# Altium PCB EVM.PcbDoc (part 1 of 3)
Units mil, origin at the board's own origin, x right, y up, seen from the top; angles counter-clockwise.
Board outline 4950 x 3450 mil, 6 copper layers (Top Layer, Power Layer 1 (PWR), Power Layer 2 (GND), Power Layer 3 (PWR), Power Layer 4 (GND), Bottom Layer), stack 58.4 mil thick; 378 components, 191 nets, 2749 pads, 0 vias.
Unrouted connection lines stored in the file: 482.
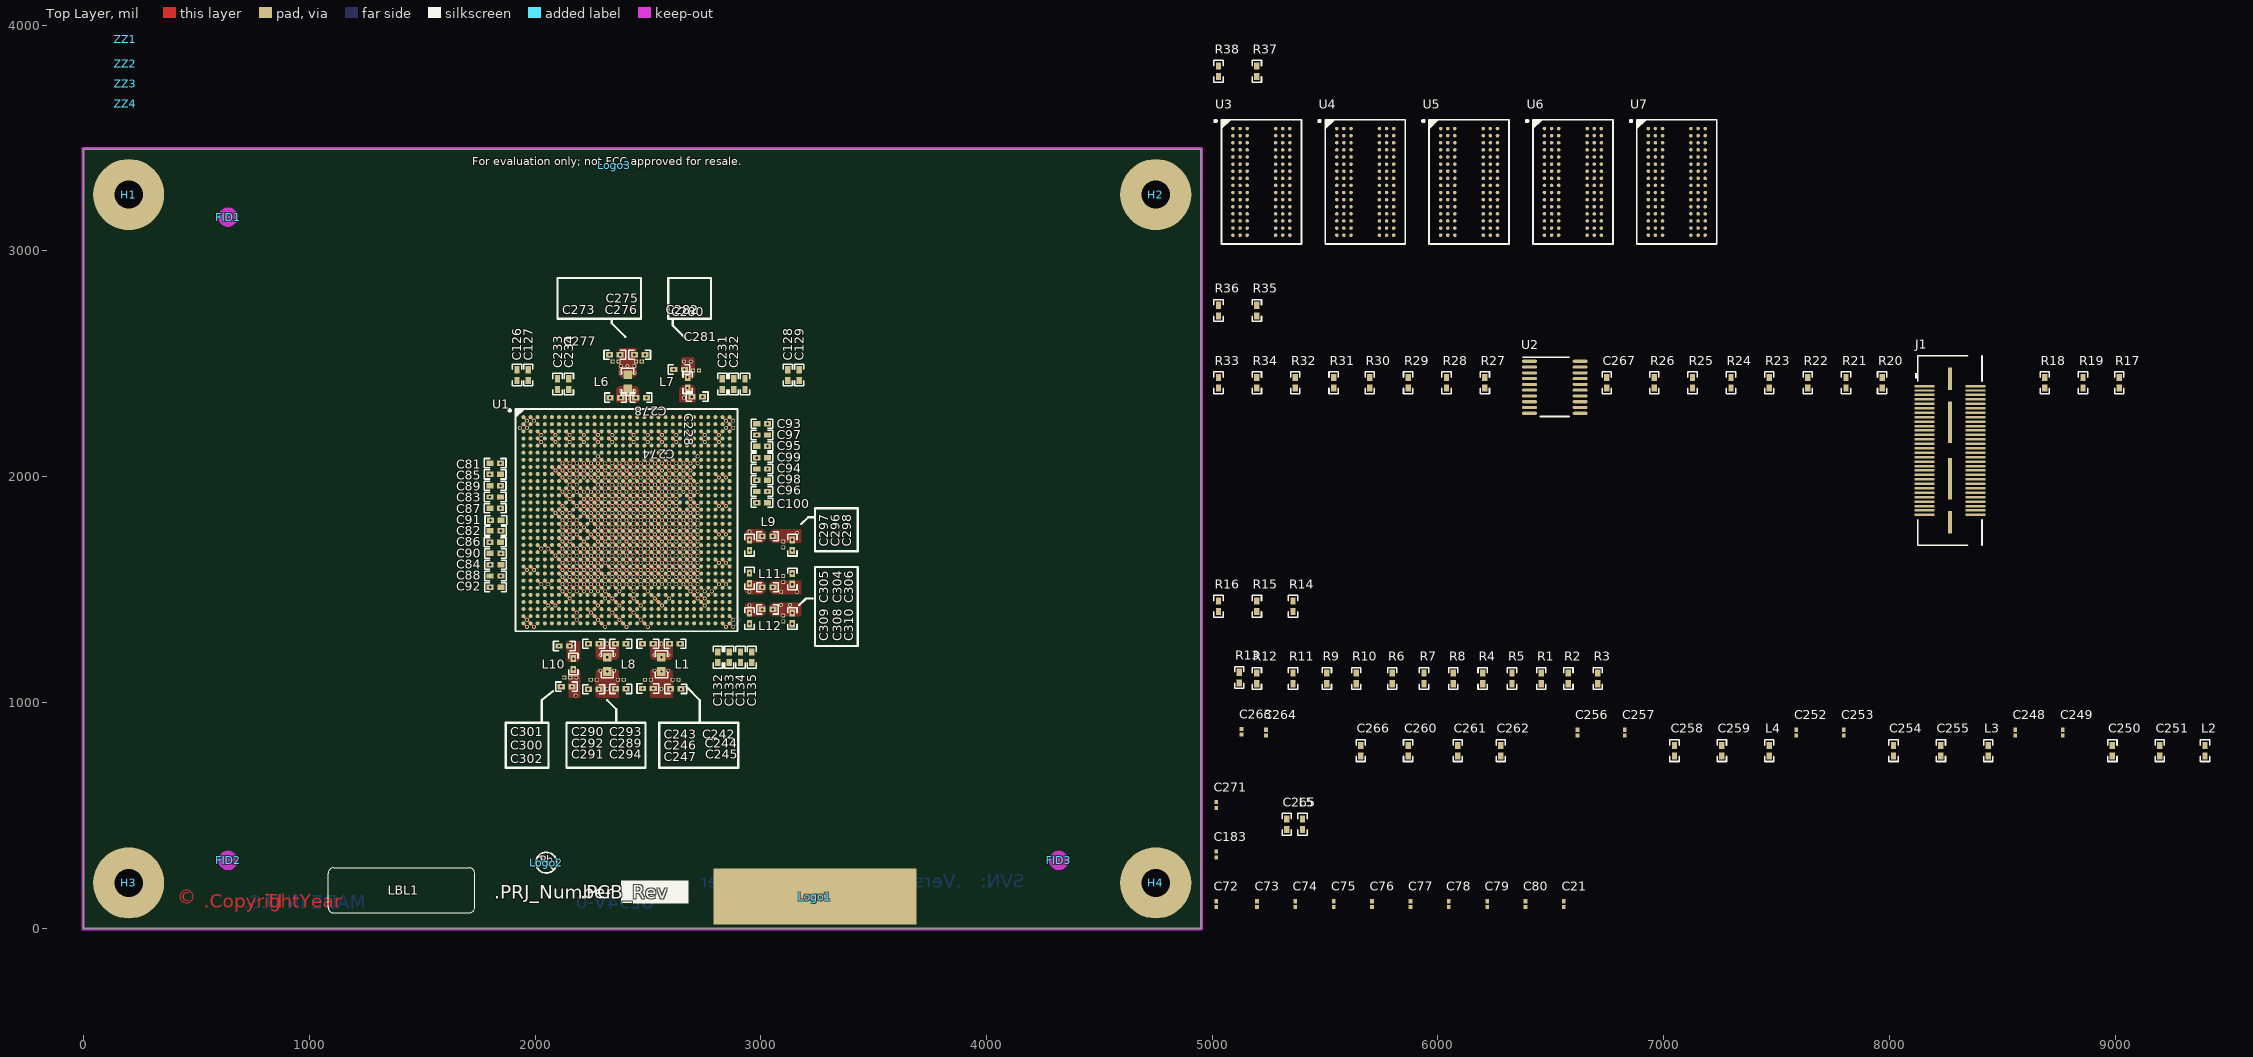
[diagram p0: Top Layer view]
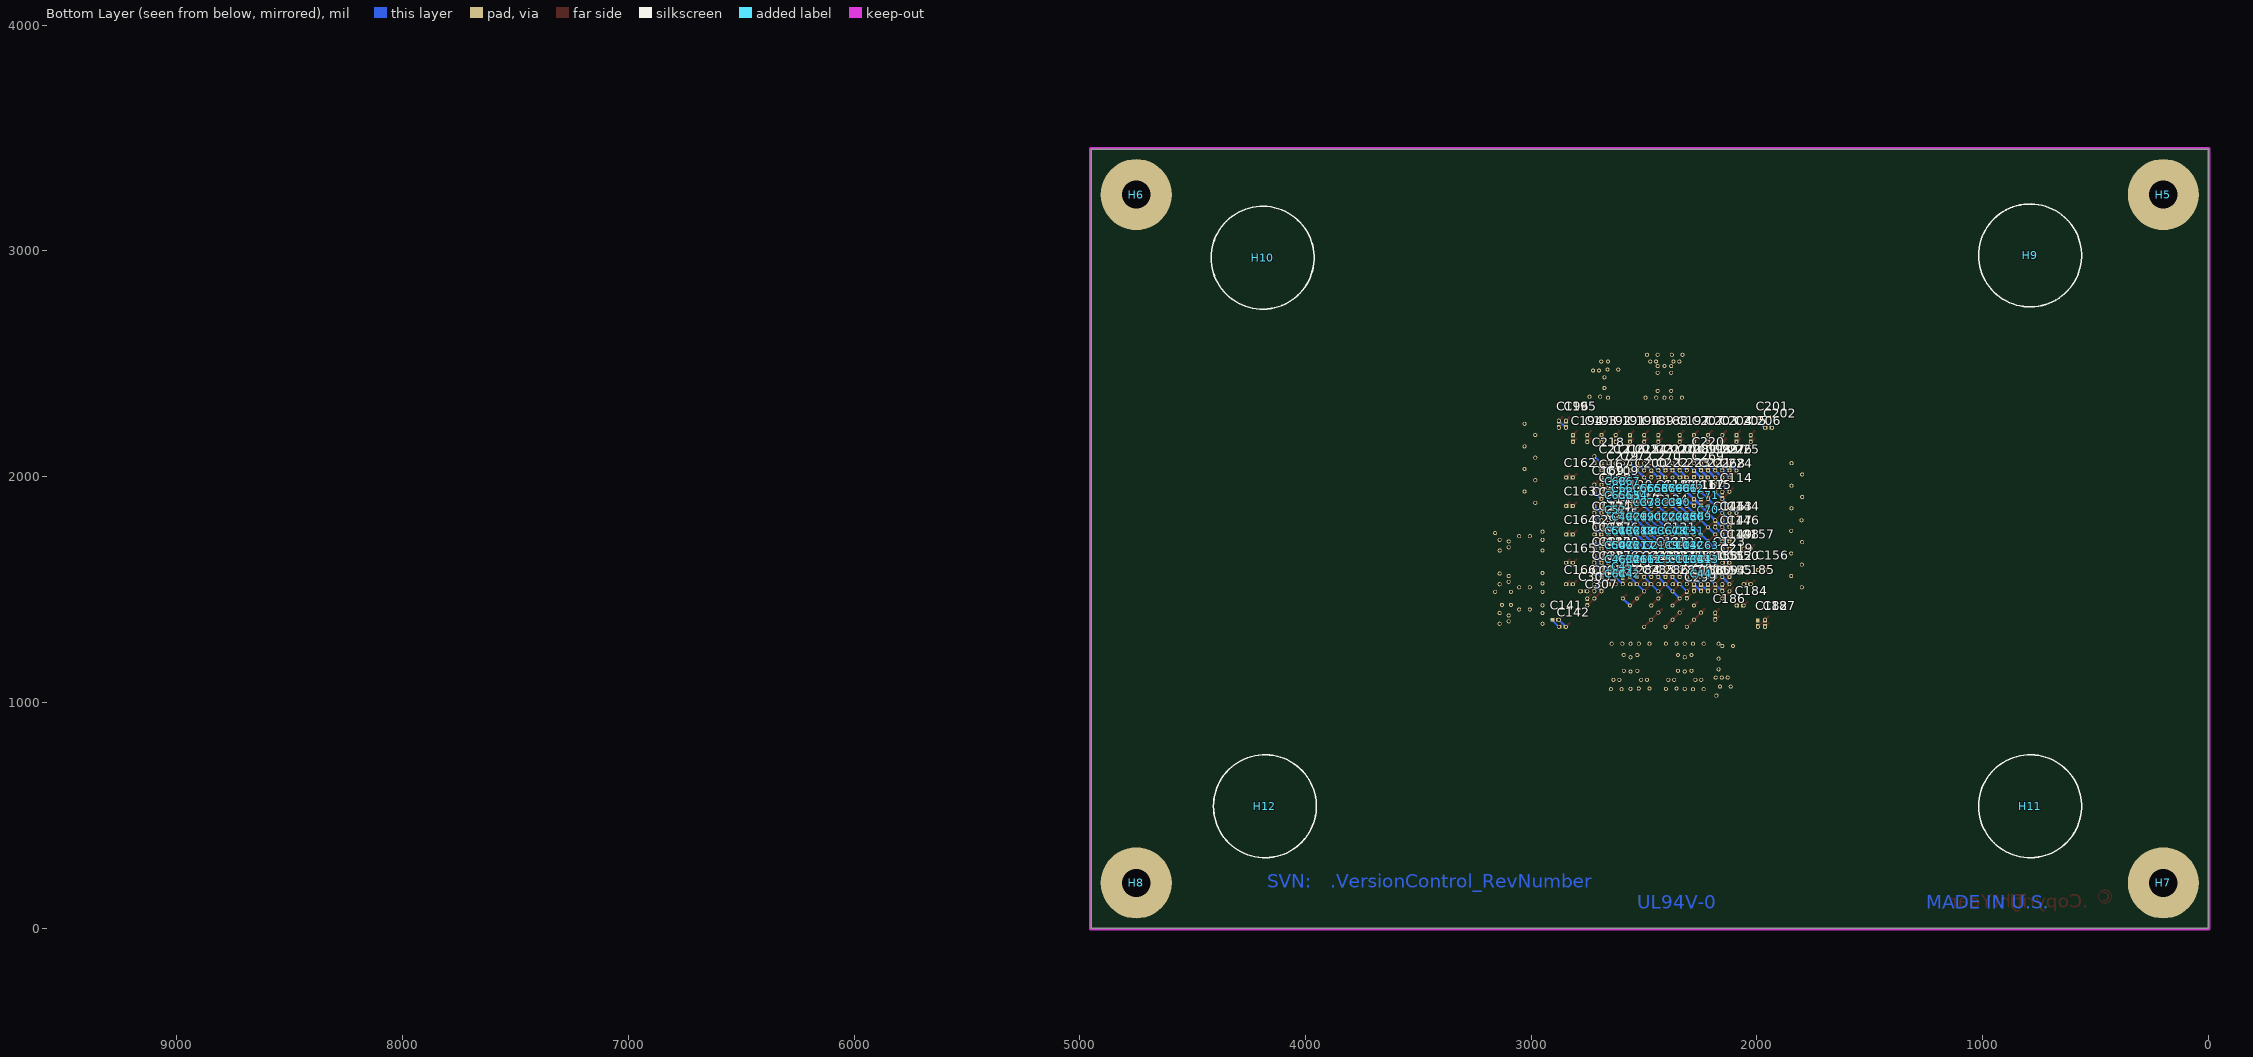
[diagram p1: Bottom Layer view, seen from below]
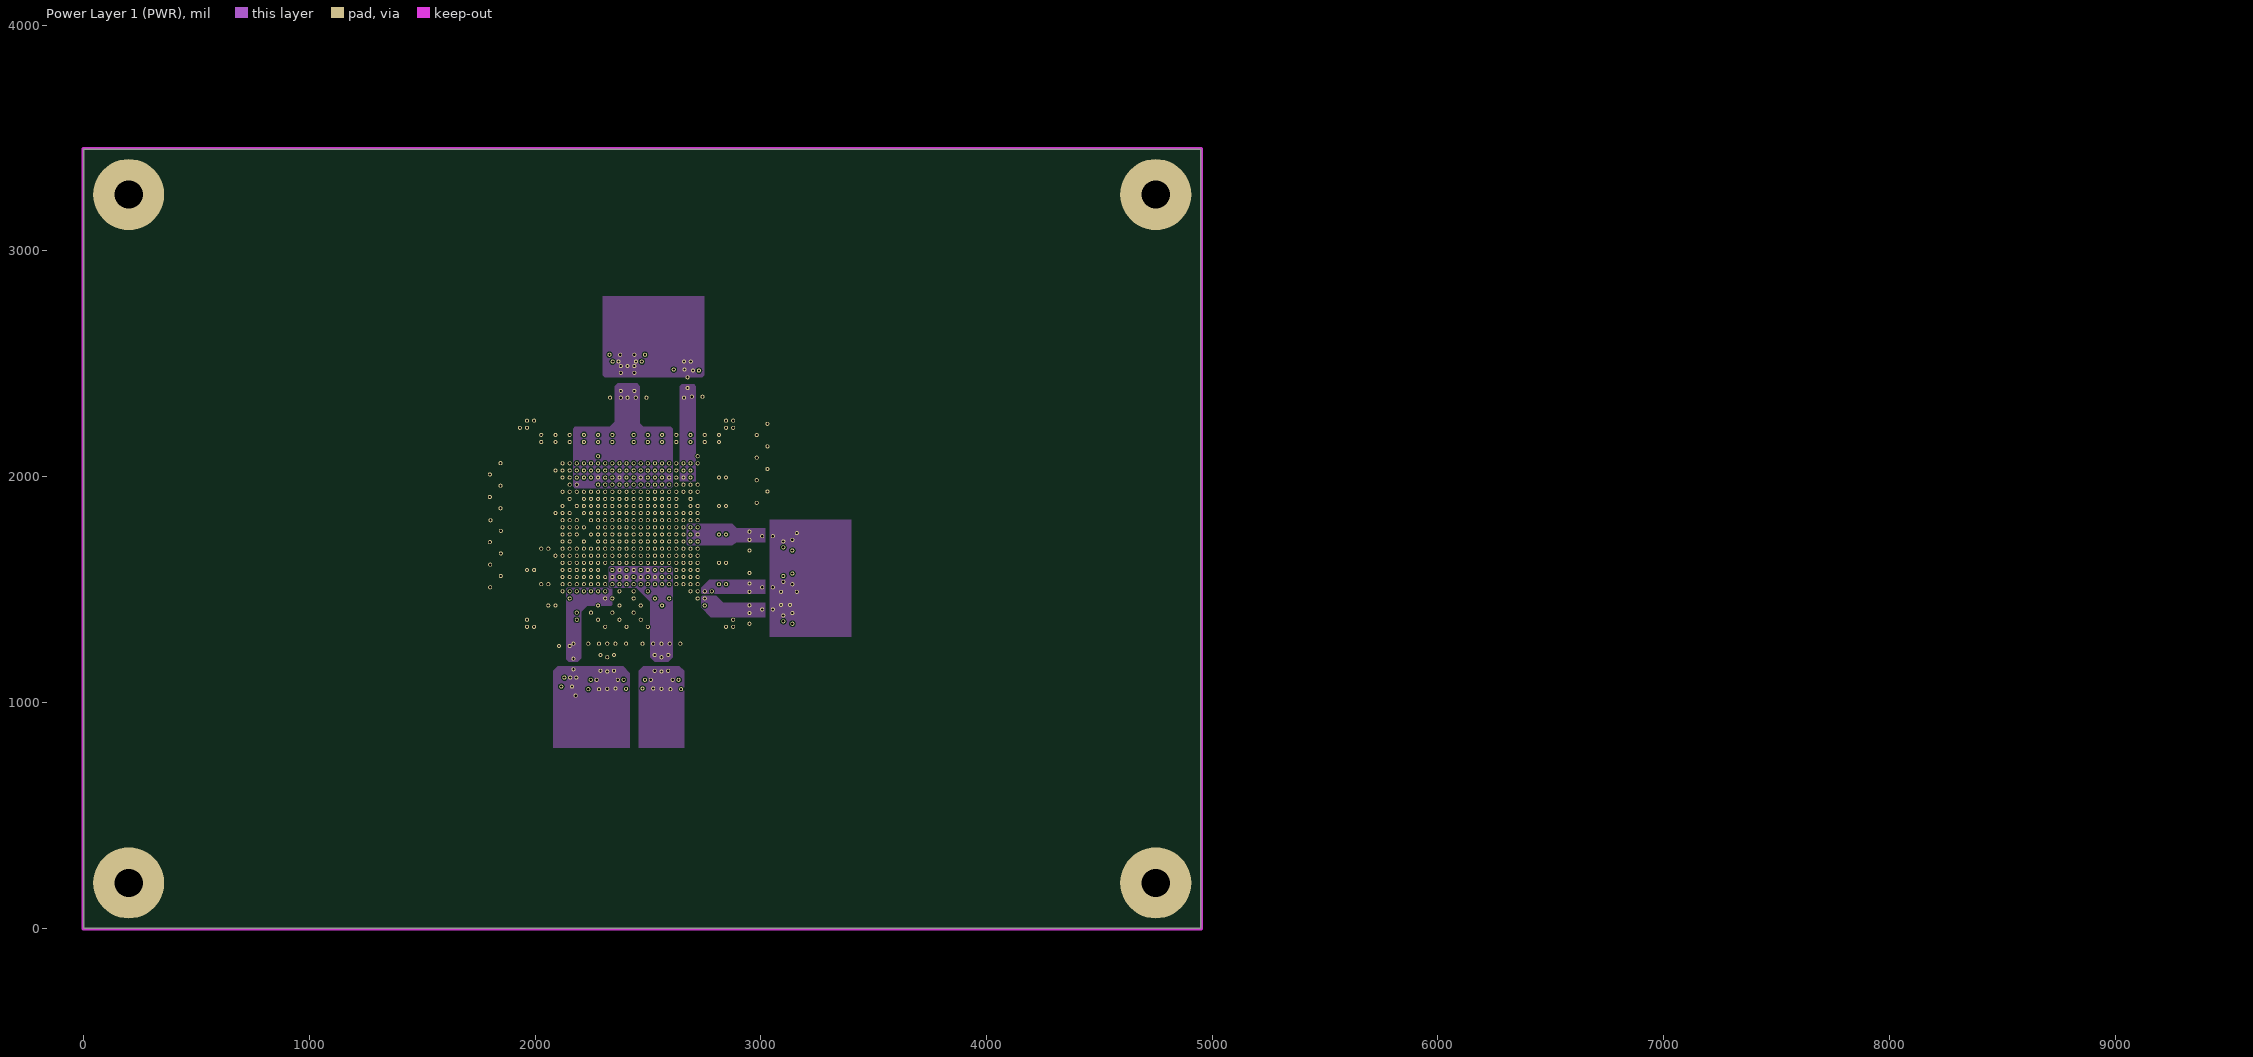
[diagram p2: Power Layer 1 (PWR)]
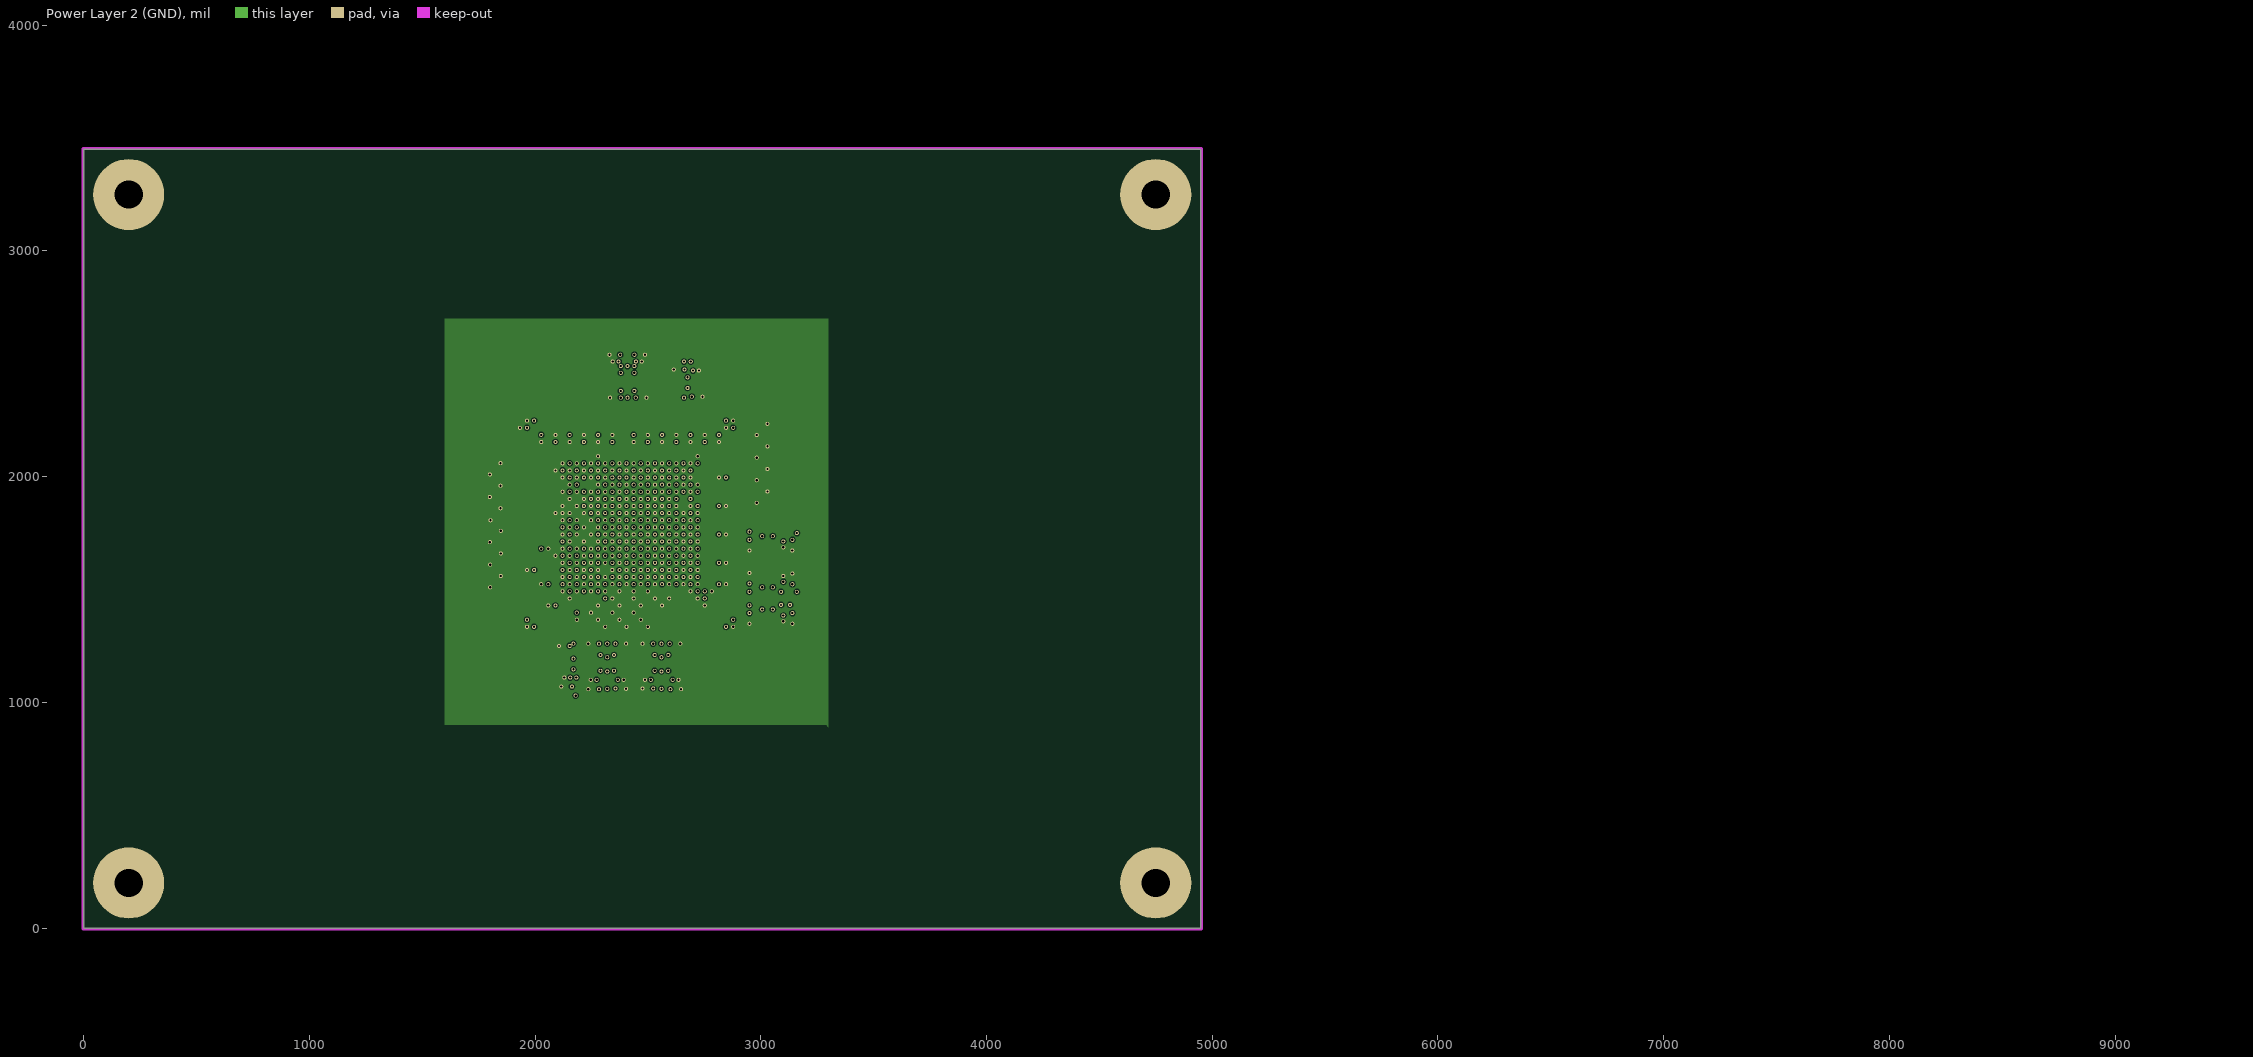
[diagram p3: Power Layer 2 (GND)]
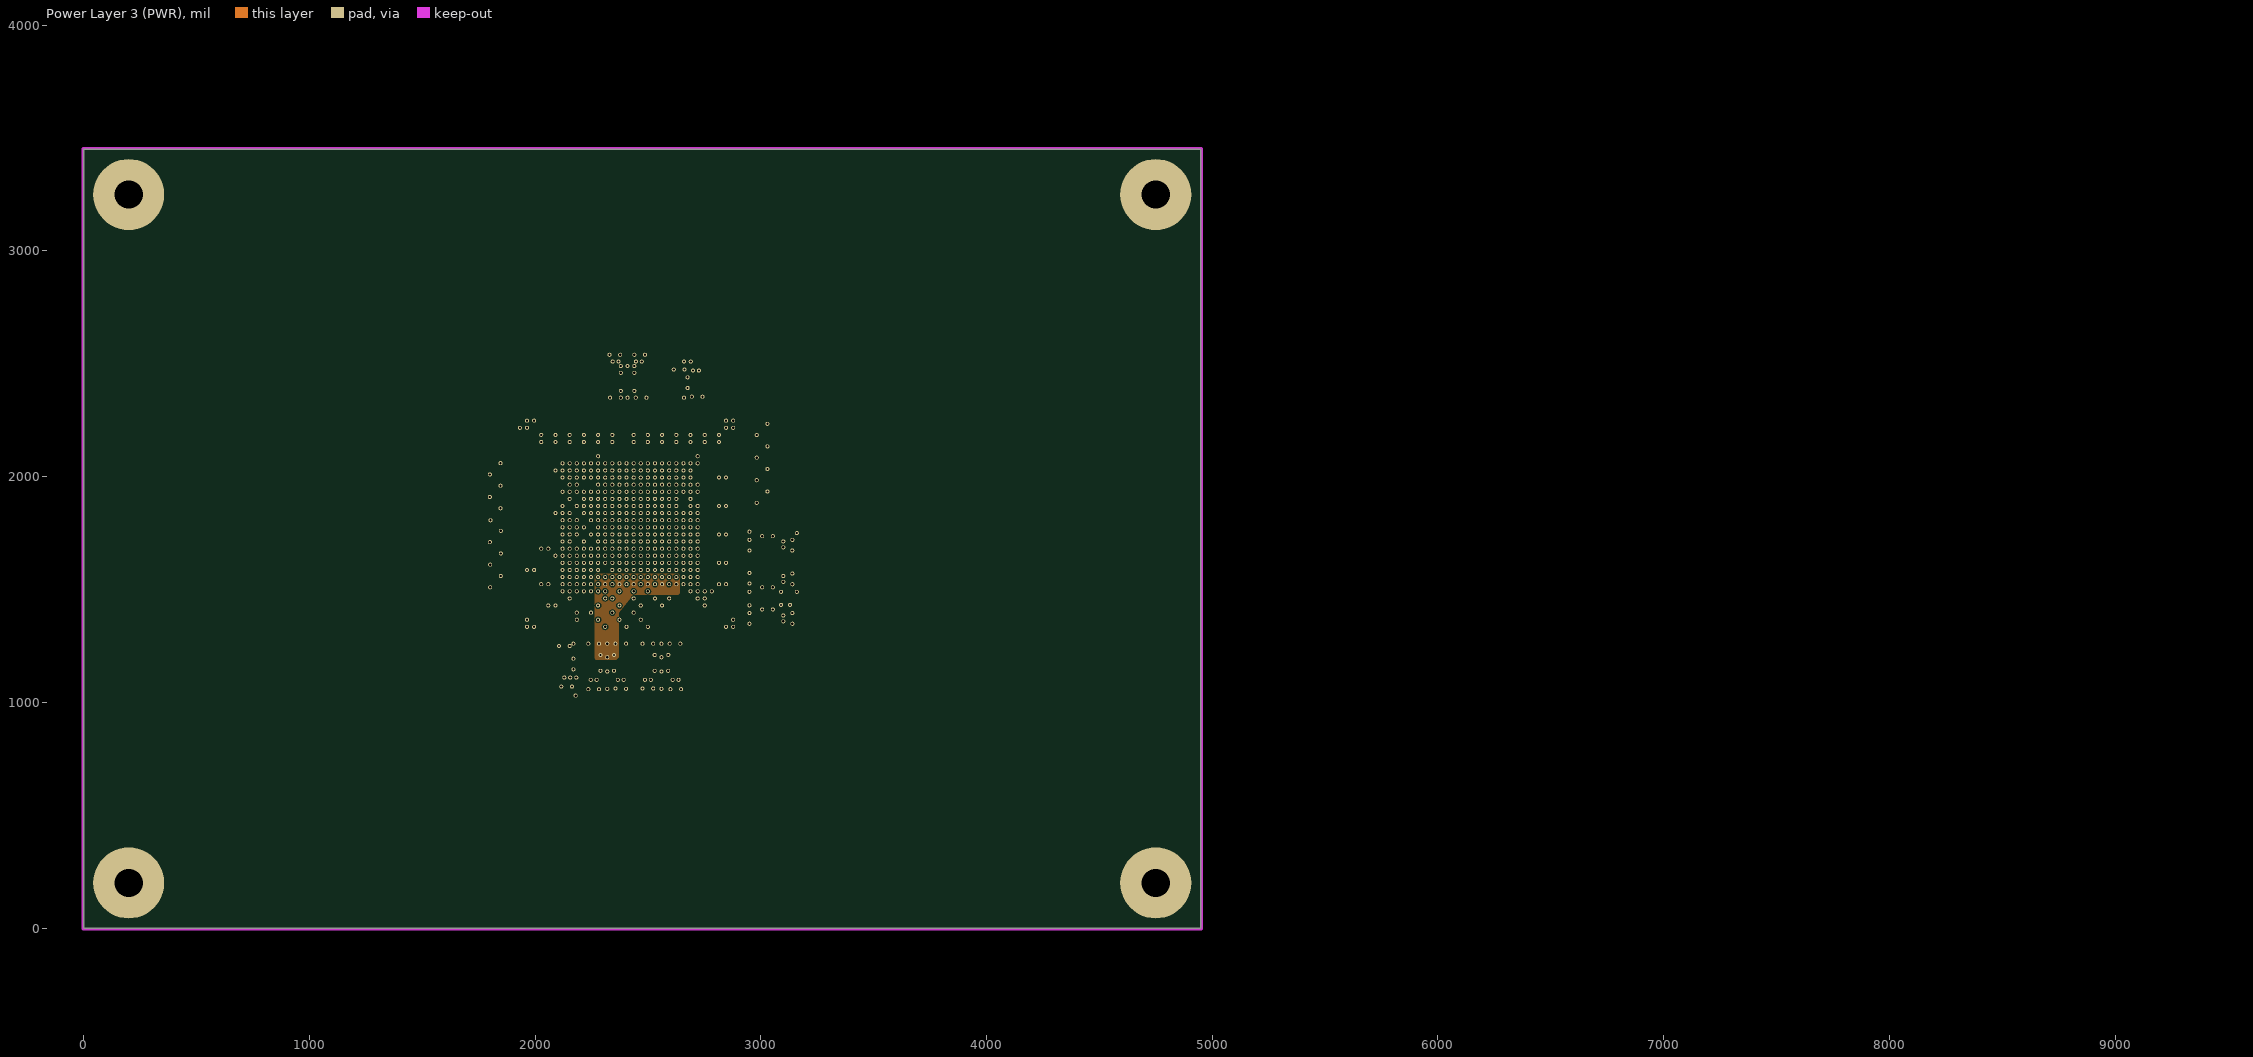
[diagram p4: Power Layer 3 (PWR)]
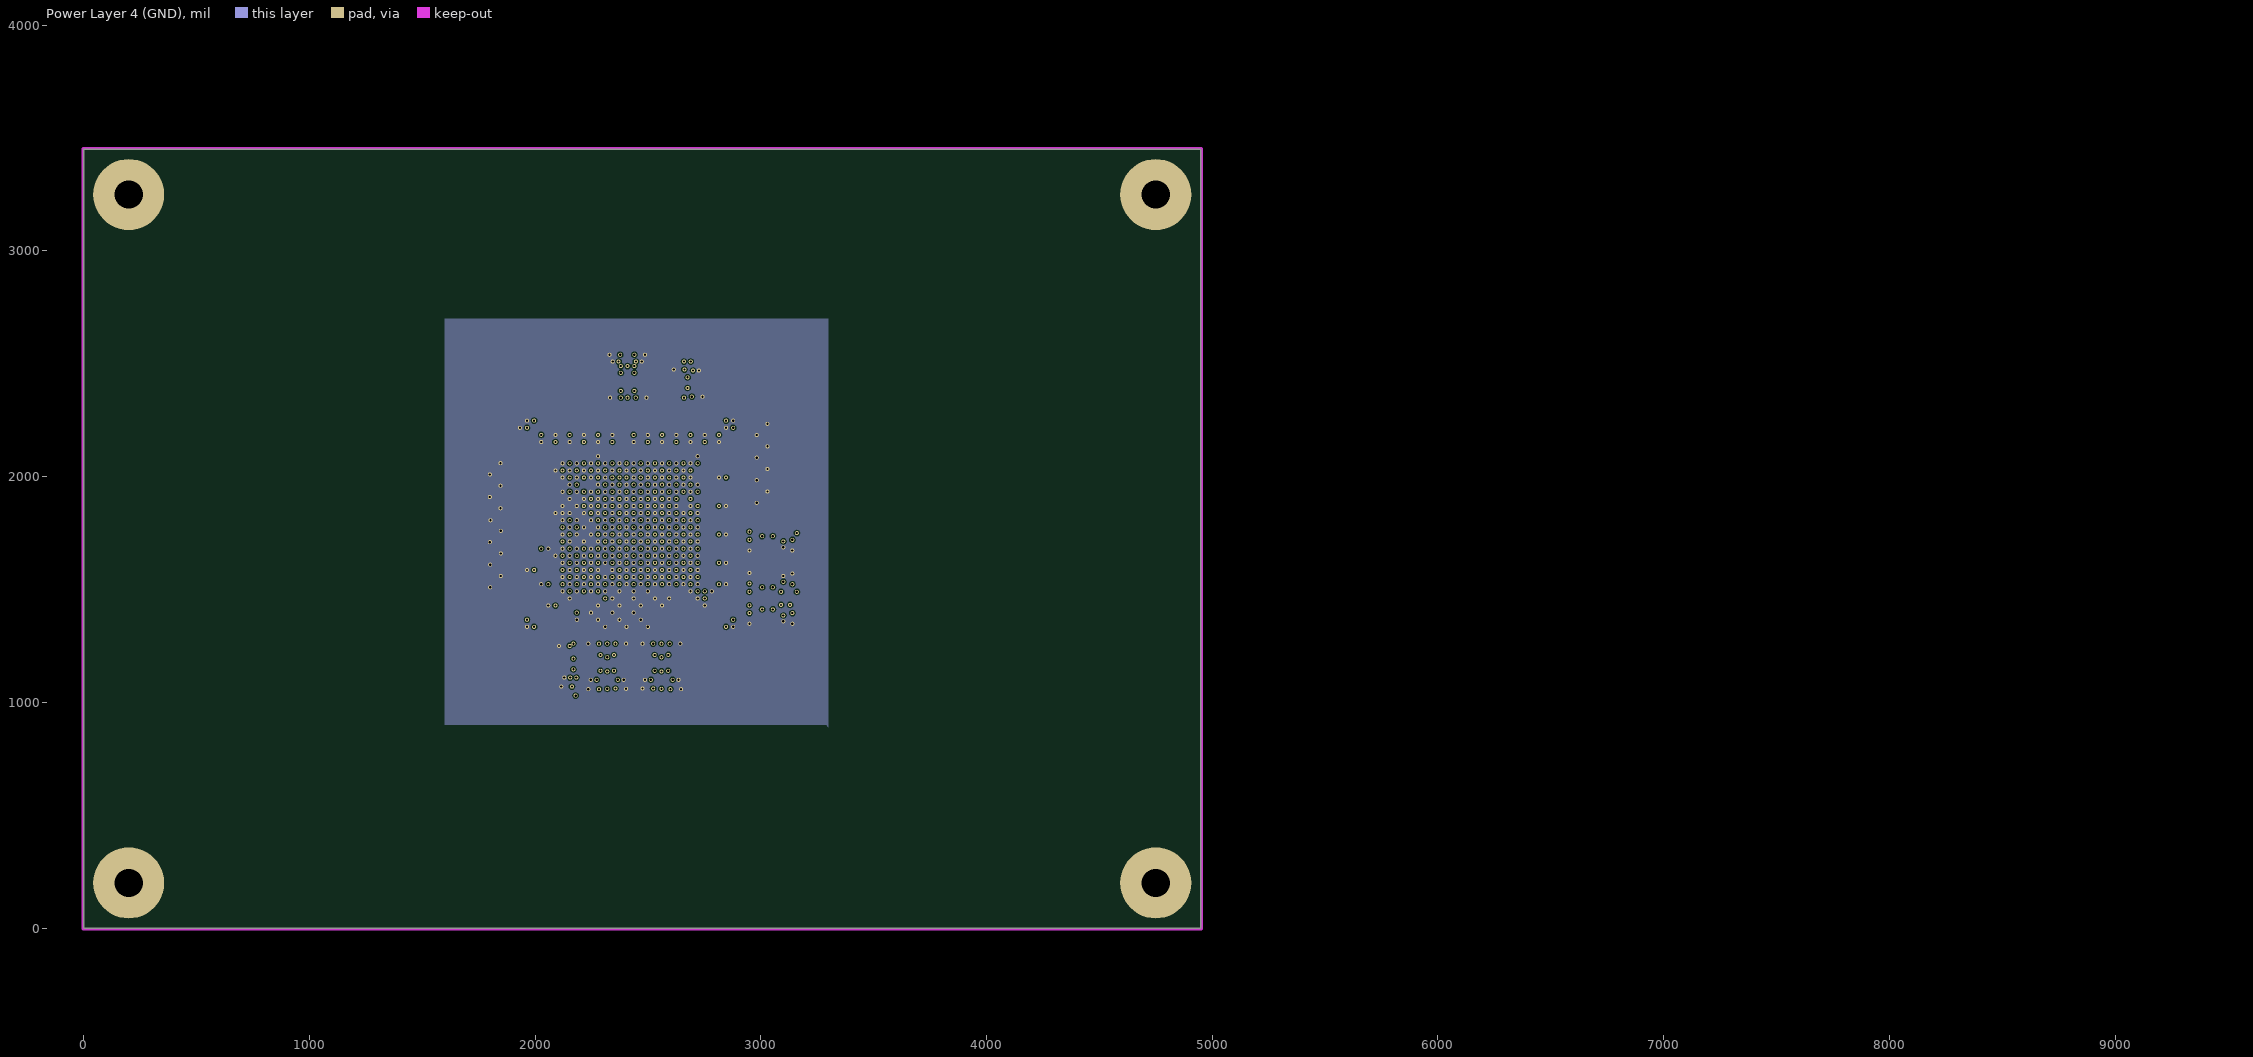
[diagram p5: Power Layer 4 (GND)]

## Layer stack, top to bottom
Top Solder: solder mask 0.4, Solder Resist, Dk 3.5
Top Layer: signal copper 1.4
Dielectric1: core 10, FR-4, Dk 4.8
Power Layer 1 (PWR): signal copper 1.4
Dielectric2: prepreg 10, FR-4, Dk 4.2
Power Layer 2 (GND): signal copper 1.4
Dielectric3: core 10, FR-4, Dk 4.2
Power Layer 3 (PWR): signal copper 1.4
Dielectric4: prepreg 10, FR-4, Dk 4.2
Power Layer 4 (GND): signal copper 1.4
Dielectric5: core 10, FR-4, Dk 4.2
Bottom Layer: signal copper 1.4
Bottom Solder: solder mask 0.4, Solder Resist, Dk 3.5

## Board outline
0,0 4950,0 4950,3450 0,3450

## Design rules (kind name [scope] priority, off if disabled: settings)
AcuteAngle [All] p1: minimum=4.50000000000000E+0001 checktracksonly=FALSE
AssemblyTestPointUsage [All] p1: valid=2
Clearance Clearance_Keepouts_0201_BGA_cap [(OnLayer('Top Layer') OR OnLayer('Bottom Layer')) vs (HasFootprint('0201') AND ( InNet('GND')OR InNet('K2L_CVDD') OR InNet('K2L_CVDD1V0')OR InNet('K2L_DVDD1V8')OR InNet('K2L_AVDDA1_1V8_FILT') OR InNet('K2L_AVDDA2_1V8_FILT') OR InNet('K2L_AVDDA3_1V8_FILT') OR InNet('K2L_AVDDA4_1V8_FILT') OR InNet('K2L_AVDDA5_1V8_FILT') OR InNet('K2L_AVDDA10_6_1V8_FILT') OR InNet('K2L_VDDAHV_1V8_FILT') OR InNet('K2L_VDDALV_FILT') OR   InNet('K2L_DVDD1V5')  )   )] p1: gap=0
Clearance Clearance_Keepouts_BGA900_0p80mm_pitch [(OnLayer('Top Layer') OR OnLayer('Bottom Layer') OR OnLayer('Multi-Layer') ) vs HasFootprint('BGA900C80P30X30_2500X2500X355')] p2: gap=3.94
Clearance Clearance_Keepouts [((IsTrack Or IsArc) And Not InPoly) And IsFree and IsKeepOut vs ((IsTrack Or IsArc) And Not InPoly) And IsFree and IsKeepOut] p3: gap=0
Clearance Clearance_BoardEdge_MountingHoles [OnCopper and InComponentClass('Mounting Holes') vs IsKeepOut] p4: gap=40
Clearance Clearance_BoardEdge_Poly [OnCopper and InPoly vs IsKeepOut] p5: gap=25
Clearance Clearance_BoardEdge [OnCopper and Not InComponentClass('Logo') and not InComponentClass('FiducialMark') and not InRegion(1000,500,4000,800) and Not IsKeepout vs IsKeepOut] p6: gap=75
Clearance Clearance_Poly1 [InPolygon vs InNet('GND')OR InNet('K2L_CVDD') OR InNet('K2L_CVDD1V0')OR InNet('K2L_DVDD1V8')OR InNet('K2L_AVDDA1_1V8_FILT') OR InNet('K2L_AVDDA2_1V8_FILT') OR InNet('K2L_AVDDA3_1V8_FILT') OR InNet('K2L_AVDDA4_1V8_FILT') OR InNet('K2L_AVDDA5_1V8_FILT') OR InNet('K2L_AVDDA10_6_1V8_FILT') OR InNet('K2L_VDDAHV_1V8_FILT') OR InNet('K2L_VDDALV_FILT') OR InNet('K2L_DVDD0V85') OR    InNet('K2L_DVDD1V5')] p7: gap=5
Clearance Clearance_Poly2 [InPolygon] p8: gap=25
Clearance [All] p9: gap=3.94
ComponentClearance ComponentClearance_MountingHoles_FiducialMarks [InComponentClass('Mounting Holes') vs InComponentClass('FiducialMark')] p1: gap=50 collisioncheckmode=3 verticalgap=10 showdistances=FALSE
ComponentClearance ComponentClearance_Shunt [InComponentClass('Header') vs InComponentClass('Shunt')] p2: gap=0 collisioncheckmode=3 verticalgap=0 showdistances=FALSE
ComponentClearance ComponentClearance_Logo [InComponentClass('Logo')] p3: gap=50 collisioncheckmode=3 verticalgap=10 showdistances=FALSE
ComponentClearance ComponentClearance_ScrewToNut [(HasFootprint('NY PMS 440 0025 PH')) vs (HasFootprint('Keystone_1902C'))] p4: gap=5 collisioncheckmode=3 verticalgap=10 showdistances=FALSE
ComponentClearance ComponentClearance_MountingHoles [InComponentClass('Mounting Holes')] p5: gap=250 collisioncheckmode=3 verticalgap=100000 showdistances=FALSE
ComponentClearance ComponentClearance_SmallPassives [HasFootprint('0201*') or HasFootprint('0402*') or HasFootprint('0508') or HasFootprint('0603*') or HasFootprint('0612') or HasFootprint('0805*') or HasFootprint('0815*') or HasFootprint('0830*') or HasFootprint('1206*') or HasFootprint('1210*') or HasFootprint('1808*') or HasFootprint('1812*') or HasFootprint('1825*') or HasFootprint('2010*') or HasFootprint('2220*') or HasFootprint('2225*') or HasFootprint('2512*') or HasFootprint('2728*') or HasFootprint('3518*') vs HasFootprint('0201*') or HasFootprint('0402*') or HasFootprint('0508') or HasFootprint('0603*') or HasFootprint('0612') or HasFootprint('0805*') or HasFootprint('0815*') or HasFootprint('0830*') or HasFootprint('1206*') or HasFootprint('1210*') or HasFootprint('1808*') or HasFootprint('1812*') or HasFootprint('1825*') or HasFootprint('2010*') or HasFootprint('2220*') or HasFootprint('2225*') or HasFootprint('2512*') or HasFootprint('2728*') or HasFootprint('3518*')] p6: gap=10 collisioncheckmode=3 verticalgap=10 showdistances=FALSE
ComponentClearance ComponentClearance_THtoSMT [IsThruComponent vs IsSMTComponent] p7: gap=100 collisioncheckmode=3 verticalgap=30 showdistances=FALSE
ComponentClearance ComponentClearance_THtoTH [IsThruComponent vs IsThruComponent] p8: gap=118.11 collisioncheckmode=3 verticalgap=30 showdistances=FALSE
ComponentClearance [All] p9: gap=40 collisioncheckmode=3 verticalgap=10 showdistances=FALSE
DiffPairsRouting [All] p1: maxlimit=100 minlimit=10 mostfreqgap=10 toplayer_minwidth=15 toplayer_maxwidth=15 toplayer_prefwidth=15 midlayer1_minwidth=15 midlayer1_maxwidth=15 midlayer1_prefwidth=15 midlayer2_minwidth=15 midlayer2_maxwidth=15 midlayer2_prefwidth=15 midlayer3_minwidth=15 midlayer3_maxwidth=15 midlayer3_prefwidth=15 midlayer4_minwidth=15 midlayer4_maxwidth=15 midlayer4_prefwidth=15 bottomlayer_minwidth=15 bottomlayer_maxwidth=15 bottomlayer_prefwidth=15 maxuncoupledlength=1000
FabricationTestPointUsage TestPointUsage [All] p1: valid=2 allowmultiple=FALSE
FabricationTestpoint Testpoint [All] p1: side=3 testpointundercomponent=TRUE minsize=40 maxsize=100 preferedsize=60 minholesize=0 maxholesize=40 preferedholesize=32 testpointgrid=1 allowsidetop=TRUE allowsidebottom=TRUE usegrid=TRUE gridtolerance=0.01
FanoutControl Fanout_LCC [IsLCC] p1: bgadir=Out bgaviamode=Centered fanoutstyle=Auto fanoutdirection=Alternating viagrid=1 // Fanout_LCC (Default Rule)
FanoutControl Fanout_BGA [IsBGA] p2: bgadir=Out bgaviamode=Centered fanoutstyle=Auto fanoutdirection=Alternating viagrid=1 // Fanout_BGA (Default Rule)
FanoutControl Fanout_Default [All] p4: bgadir=Out bgaviamode=Centered fanoutstyle=Auto fanoutdirection=Alternating viagrid=1 // Fanout_Default (Default Rule)
FanoutControl Fanout_Small [(CompPinCount < 5)] p5: bgadir=Out bgaviamode=Centered fanoutstyle=Auto fanoutdirection=OutThenIn viagrid=1 // Fanout_Small (Default Rule)
HoleSize [All] p1: absolutevalues=TRUE maxlimit=251 minlimit=8 maxpercent=80.000 minpercent=20.000
MinimumAnnularRing MinimumAnnularRing_ThermalPadVias [IsVia and InAnyComponent] p1: minimumring=5.91
MinimumAnnularRing [All] p2: minimumring=9
MinimumSolderMaskSliver MinimumSolderMaskSliver_Logo [InComponentClass('Logo') vs InComponentClass('Logo')] p1: minsoldermaskwidth=0.7
MinimumSolderMaskSliver [All] p2: minsoldermaskwidth=3.94
PlaneClearance [All] p1: clearance=10
PlaneConnect [All] p1: planeconnectstyle=Direct reliefexpansion=10 reliefentries=4 reliefconductorwidth=10 reliefairgap=10
PolygonConnect [All] p1: connectstyle=Direct reliefconductorwidth=10 reliefentries=4 polygonreliefangle="90 Angle" airgapwidth=10
RoutingVias ThermalPadVias [IsVia and InAnyComponent] p1: holewidth=7.87 width=19.68 viastyle="Through Hole" minholewidth=7.87 minwidth=19.68 maxholewidth=12.99 maxwidth=23.62
RoutingVias [All] p2: holewidth=16 width=34 viastyle="Through Hole" minholewidth=7.87 minwidth=26 maxholewidth=40 maxwidth=65
SilkToBoardRegionClearance [Not ((IsComment or IsDesignator) And (Hide <> 'False')) and not InRegion(1000,500,4000,800)] p1:
SilkToSilkClearance SilkToSilkClearance_Pb-FreeLogo [(HasFootprint('Pb-Free_Overlay_Medium') OR HasFootprint('Pb-Free_Overlay_Small')) vs (HasFootprint('Pb-Free_Overlay_Medium') OR HasFootprint('Pb-Free_Overlay_Small'))] p1: silktosilkclearance=0
SilkToSilkClearance [All] p2: silktosilkclearance=5
SilkToSolderMaskClearance "Silk to Solder Mask Opening" [All] p1: minsilkscreentomaskgap=1 clearancetoexposedcopper=FALSE
SolderMaskExpansion [All] p1: expansion=1.97
UnpouredPolygon [All] p1: allowunpoured=FALSE
Width [All] p1: maxlimit=100 minlimit=6 preferedwidth=10 checkconnectedcopper=TRUE
13 further rules are at their usual default settings.

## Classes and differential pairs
component class k2l_soc_14: R37 R38
component class k2l_soc_09_1: U3 U4 U5 U6 U7
component class k2l_soc_08: R35 R36
component class k2l_soc_07: C267 J1 R17 R18 R19 R20 R21 R22 R23 R24 R25 R26 R27 R28 R29 R30 R31 R32 R33 R34 U2
component class k2l_soc_06: R14 R15 R16
component class k2l_soc_05: R1 R2 R3 R4 R5 R6 R7 R8 R9 R10 R11 R12 R13
component class k2l_soc_03_1: C268 C269 C270 C271 C272 C273 C274 C275 C276 C277 C278 C279 C280 C281 C282 C283 C284 C285 C286 C287 C288 C289 C290 C291 C292 C293 C294 C295 C296 C297 C298 C299 C300 C301 C302 C303 C304 C305 C306 C307 C308 C309 C310 L6 L7 L8 L9 L10 L11 L12
component class k2l_soc_04: C235 C236 C237 C238 C239 C240 C241 C242 C243 C244 C245 C246 C247 C248 C249 C250 C251 C252 C253 C254 C255 C256 C257 C258 C259 C260 C261 C262 C263 C264 C265 C266 L1 L2 L3 L4 L5
component class k2l_soc_03: C109 C110 C111 C112 C113 C114 C115 C116 C117 C118 C119 C120 C121 C122 C123 C124 C126 C127 C128 C129 C132 C133 C134 C135 C136 C137 C138 C139 C140 C141 C142 C143 C144 C145 C146 C147 C148 C149 C150 C151 C152 C153 C154 C155 C156 C157 C158 C159 C160 C161 C162 C163 C164 C165 C166 C167 C168 C169 C170 C171 C172 C173 C174 C175 C176 C177 C178 C179 C180 C181 C182 C183 C184 C185 C186 C187 C188 C189 C190 C191 C192 C193 C194 C195 C196 C197 C198 C199 C200 C201 C202 C203 C204 C205 C206 C207 C208 C209 C210 C211 C212 C213 C214 C215 C216 C217 C218 C219 C220 C221 C222 C223 C224 C225 C226 C227 C228 C231 C232 C233 C234
component class k2l_soc_02: C1 C2 C3 C4 C5 C6 C7 C8 C9 C10 C11 C12 C13 C14 C15 C16 C17 C18 C19 C20 C21 C22 C23 C24 C25 C26 C27 C28 C29 C30 C31 C32 C33 C34 C35 C36 C37 C38 C39 C40 C41 C42 C43 C44 C45 C46 C47 C48 C49 C50 C51 C52 C53 C54 C55 C56 C57 C58 C59 C60 C61 C62 C63 C64 C65 C66 C67 C68 C69 C70 C71 C72 C73 C74 C75 C76 C77 C78 C79 C80 C81 C82 C83 C84 C85 C86 C87 C88 C89 C90 C91 C92 C93 C94 C95 C96 C97 C98 C99 C100
component class k2l_soc_01: U1
component class Label: LBL1
component class AssemblyNote: ZZ1 ZZ2 ZZ3 ZZ4
component class FiducialMark: FID1 FID2 FID3
component class EVM_Hardware: FID1 FID2 FID3 H1 H2 H3 H4 H5 H6 H7 H8 H9 H10 H11 H12 LBL1 Logo1 Logo2 Logo3 ZZ1 ZZ2 ZZ3 ZZ4
component class Logo: Logo1
component class "Mounting Holes": H1 H2 H3 H4

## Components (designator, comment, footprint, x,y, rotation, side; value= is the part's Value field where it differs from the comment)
C1 "GRM033R71E102KA01D" 0201 2437.01,1696.85 r270 bottom
C2 "GRM033R71E102KA01D" 0201 2468.5,1696.85 r90 bottom
C3 "GRM033R71E102KA01D" 0201 2437.01,1759.84 r270 bottom
C4 "GRM033R71E102KA01D" 0201 2468.5,1759.84 r90 bottom
C5 "GRM033R71E102KA01D" 0201 2405.51,1633.86 r90 bottom
C6 "GRM033R71E102KA01D" 0201 2405.51,1759.84 r90 bottom
C7 "GRM033R71E102KA01D" 0201 2374.02,1759.84 r270 bottom
C8 "GRM033R71E102KA01D" 0201 2342.52,1759.84 r90 bottom
C9 "GRM033R71E102KA01D" 0201 2374.02,1696.85 r270 bottom
C10 "GRM033R71E102KA01D" 0201 2342.52,1696.85 r90 bottom
C11 "GRM033R71E102KA01D" 0201 2342.52,1633.86 r90 bottom
C12 "GRM033R71E102KA01D" 0201 2468.5,1633.86 r90 bottom
C13 "GRM033R71E102KA01D" 0201 2311.02,1633.86 r270 bottom
C14 "GRM033R71E102KA01D" 0201 2311.02,1696.85 r270 bottom
C15 "GRM033R71E102KA01D" 0201 2311.02,1759.84 r270 bottom
C16 "GRM033R71E102KA01D" 0201 2500,1633.86 r270 bottom
C17 "GRM033R71E102KA01D" 0201 2500,1696.85 r270 bottom
C18 "GRM033R71E102KA01D" 0201 2500,1759.84 r270 bottom
C19 "GRM033R71E102KA01D" 0201 2500,1822.83 r270 bottom
C20 "GRM033R71E102KA01D" 0201 2468.5,1822.83 r90 bottom
C21 "GRM033R71E102KA01D" 0201 6558,106 r90 top
C22 "GRM033R71E102KA01D" 0201 2405.51,1822.83 r90 bottom
C23 "GRM033R71E102KA01D" 0201 2374.02,1822.83 r270 bottom
C24 "GRM033R71E102KA01D" 0201 2342.52,1822.83 r90 bottom
C25 "GRM033R71E102KA01D" 0201 2311.02,1822.83 r270 bottom
C26 "GRM033R71E102KA01D" 0201 2531.5,1633.86 r90 bottom
C27 "GRM033R71E102KA01D" 0201 2531.5,1696.85 r90 bottom
C28 "GRM033R71E102KA01D" 0201 2531.5,1759.84 r90 bottom
C29 "GRM033R71E102KA01D" 0201 2531.5,1822.83 r90 bottom
C30 "GRM033R71E102KA01D" 0201 2279.53,1822.83 r90 bottom
C31 "GRM033R71E102KA01D" 0201 2279.53,1759.84 r90 bottom
C32 "GRM033R71E102KA01D" 0201 2279.53,1696.85 r90 bottom
C33 "GRM033R71E102KA01D" 0201 2279.53,1633.86 r90 bottom
C34 "GRM033R71E102KA01D" 0201 2562.99,1633.86 r270 bottom
C35 "GRM033R71E102KA01D" 0201 2562.99,1696.85 r270 bottom
C36 "GRM033R71E102KA01D" 0201 2562.99,1759.84 r270 bottom
C37 "GRM033R71E102KA01D" 0201 2500,1885.83 r270 bottom
C38 "GRM033R71E102KA01D" 0201 2468.5,1885.83 r90 bottom
C39 "GRM033R71E102KA01D" 0201 2374.02,1885.83 r270 bottom
C40 "GRM033R71E102KA01D" 0201 2342.52,1885.83 r90 bottom
C41 "GRM033R71E102KA01D" 0201 2248.03,1633.86 r270 bottom
C42 "GRM033R71E102KA01D" 0201 2562.99,1570.87 r270 bottom
C43 "GRM033R71E102KA01D" 0201 2216.54,1633.86 r90 bottom
C44 "GRM033R71E102KA01D" 0201 2248.03,1570.87 r270 bottom
C45 "GRM033R71E102KA01D" 0201 2594.49,1602.36 r270 bottom
C46 "GRM033R71E102KA01D" 0201 2625.98,1633.86 r270 bottom
C47 "GRM033R71E102KA01D" 0201 2594.49,1696.85 r90 bottom
C48 "GRM033R71E102KA01D" 0201 2594.49,1759.84 r90 bottom
C49 "GRM033R71E102KA01D" 0201 2594.49,1822.83 r90 bottom
C50 "GRM033R71E102KA01D" 0201 2625.98,1696.85 r270 bottom
C51 "GRM033R71E102KA01D" 0201 2625.98,1759.84 r270 bottom
C52 "GRM033R71E102KA01D" 0201 2625.98,1854.33 r90 bottom
C53 "GRM033R71E102KA01D" 0201 2562.99,1917.32 r90 bottom
C54 "GRM033R71E102KA01D" 0201 2531.5,1917.32 r270 bottom
C55 "GRM033R71E102KA01D" 0201 2468.5,1948.82 r90 bottom
C56 "GRM033R71E102KA01D" 0201 2500,1948.82 r270 bottom
C57 "GRM033R71E102KA01D" 0201 2405.51,1948.82 r90 bottom
C58 "GRM033R71E102KA01D" 0201 2437.01,1948.82 r270 bottom
C59 "GRM033R71E102KA01D" 0201 2374.02,1948.82 r270 bottom
C60 "GRM033R71E102KA01D" 0201 2342.52,1948.82 r90 bottom
C61 "GRM033R71E102KA01D" 0201 2311.02,1948.82 r270 bottom
C62 "GRM033R71E102KA01D" 0201 2279.53,1948.82 r90 bottom
C63 "GRM033R71E102KA01D" 0201 2216.54,1696.85 r90 bottom
C64 "GRM033R71E102KA01D" 0201 2625.98,1570.87 r270 bottom
C65 "GRM033R71E102KA01D" 0201 2625.98,1917.32 r90 bottom
C66 "GRM033R71E102KA01D" 0201 2594.49,1948.82 r90 bottom
C67 "GRM033R71E102KA01D" 0201 2562.99,1980.32 r90 bottom
C68 "GRM033R71E102KA01D" 0201 2625.98,1980.32 r90 bottom
C69 "GRM033R71E102KA01D" 0201 2248.03,1822.83 r270 bottom
C70 "GRM033R71E102KA01D" 0201 2216.54,1854.33 r270 bottom
C71 "GRM033R71E102KA01D" 0201 2216.54,1917.32 r270 bottom
C72 "GRM033R71E102KA01D" 0201 5018,106 r90 top
C73 "GRM033R71E102KA01D" 0201 5198,106 r90 top
C74 "GRM033R71E102KA01D" 0201 5368,106 r90 top
C75 "GRM033R71E102KA01D" 0201 5538,106 r90 top
C76 "GRM033R71E102KA01D" 0201 5708,106 r90 top
C77 "GRM033R71E102KA01D" 0201 5878,106 r90 top
C78 "GRM033R71E102KA01D" 0201 6048,106 r90 top
C79 "GRM033R71E102KA01D" 0201 6218,106 r90 top
C80 "GRM033R71E102KA01D" 0201 6388,106 r90 top
C81 "GRM152B30J104KE19" 0402 1823.62,2060 r0 top
C82 "GRM152B30J104KE19" 0402 1825,1760 r0 top
C83 "GRM152B30J104KE19" 0402 1823.62,1910 r180 top
C84 "GRM152B30J104KE19" 0402 1825,1610 r180 top
C85 "GRM152B30J104KE19" 0402 1823.62,2010 r180 top
C86 "GRM152B30J104KE19" 0402 1823.62,1710 r180 top
C87 "GRM152B30J104KE19" 0402 1823.62,1860 r0 top
C88 "GRM152B30J104KE19" 0402 1825,1560 r0 top
C89 "GRM152B30J104KE19" 0402 1823.62,1960 r0 top
C90 "GRM152B30J104KE19" 0402 1825,1660 r0 top
C91 "GRM152B30J104KE19" 0402 1826.38,1806.65 r180 top
C92 "GRM152B30J104KE19" 0402 1825,1510 r180 top
C93 "GRM152B30J104KE19" 0402 3005.91,2234.25 r0 top
C94 "GRM152B30J104KE19" 0402 3005.91,2034.25 r0 top
C95 "GRM152B30J104KE19" 0402 3005.91,2134.25 r0 top
C96 "GRM152B30J104KE19" 0402 3005.91,1934.25 r0 top
C97 "GRM152B30J104KE19" 0402 3005.91,2184.25 r180 top
C98 "GRM152B30J104KE19" 0402 3005.91,1984.25 r180 top
C99 "GRM152B30J104KE19" 0402 3005.91,2084.25 r180 top
C100 "GRM152B30J104KE19" 0402 3005.91,1884.25 r180 top
C109 "GRM033R71E102KA01D" 0201 2657.48,1948.82 r90 bottom
C110 "GRM033R71E102KA01D" 0201 2562.99,1822.83 r270 bottom
C111 "GRM033R71E102KA01D" 0201 2594.49,1539.37 r270 bottom
C112 "GRM033R71E102KA01D" 0201 2547.24,1870.08 r0 bottom
C113 "GRM033R71E102KA01D" 0201 2437.01,1633.86 r270 bottom
C114 "GRM033R71E102KA01D" 0201 2153.54,1917.32 r270 bottom
C115 "GRM033R71E102KA01D" 0201 2248.03,1885.83 r270 bottom
C116 "GRM033R71E102KA01D" 0201 2311.02,1885.83 r270 bottom
C117 "GRM033R71E102KA01D" 0201 2279.53,1885.83 r90 bottom
C118 "GRM033R71E102KA01D" 0201 2437.01,1885.83 r270 bottom
C119 "GRM033R71E102KA01D" 0201 2405.51,1885.83 r90 bottom
C120 "GRM033R71E102KA01D" 0201 2594.49,1885.83 r90 bottom
C121 "GRM033R71E102KA01D" 0201 2405.51,1696.85 r90 bottom
C122 "GRM033R71E102KA01D" 0201 2374.02,1633.86 r270 bottom
C123 "GRM033R71E102KA01D" 0201 2185.04,1633.86 r270 bottom
C124 "GRM033R71E102KA01D" 0201 2437.01,1822.83 r270 bottom
C126 "GRM152B30J104KE19" 0402 1920,2450 r90 top
C127 "GRM152B30J104KE19" 0402 1970,2450 r270 top
C128 "GRM152B30J104KE19" 0402 3120,2450 r90 top
C129 "GRM152B30J104KE19" 0402 3170,2450 r270 top
C132 "GRM152B30J104KE19" 0402 2810,1200 r270 top
C133 "GRM152B30J104KE19" 0402 2860,1200 r90 top
C134 "GRM152B30J104KE19" 0402 2910,1200 r270 top
C135 "GRM152B30J104KE19" 0402 2960,1200 r270 top
C136 "GRM033R71E102KA01D" 0201 2657.48,1570.87 r90 bottom
C137 "GRM033R71E102KA01D" 0201 2688.98,1570.87 r270 bottom
C138 "GRM033R71E102KA01D" 0201 2720.47,1570.87 r90 bottom
C139 "GRM033R71E102KA01D" 0201 2720.47,1507.87 r90 bottom
C140 "GRM033R71E102KA01D" 0201 2688.98,1507.87 r270 bottom
C141 "GRM033R71E102KA01D" 0201 2893.7,1366.14 r0 bottom
C142 "GRM033R71E102KA01D" 0201 2862.2,1334.65 r0 bottom
C143 "GRM033R71E102KA01D" 0201 2153.54,1791.34 r270 bottom
C144 "GRM033R71E102KA01D" 0201 2122.05,1791.34 r90 bottom
C145 "GRM033R71E102KA01D" 0201 2185.04,1791.34 r90 bottom
C146 "GRM033R71E102KA01D" 0201 2122.05,1728.35 r90 bottom
C147 "GRM033R71E102KA01D" 0201 2153.54,1728.35 r270 bottom
C148 "GRM033R71E102KA01D" 0201 2122.05,1665.35 r90 bottom
C149 "GRM033R71E102KA01D" 0201 2153.54,1665.35 r270 bottom
C150 "GRM033R71E102KA01D" 0201 2122.05,1570.87 r270 bottom
C151 "GRM033R71E102KA01D" 0201 2185.04,1570.87 r270 bottom
C152 "GRM033R71E102KA01D" 0201 2153.54,1570.87 r90 bottom
C153 "GRM033R71E102KA01D" 0201 2216.54,1570.87 r90 bottom
C154 "GRM033R71E102KA01D" 0201 2185.04,1507.87 r270 bottom
C155 "GRM033R71E102KA01D" 0201 2153.54,1507.87 r90 bottom
C156 "GRM033R71E102KA01D" 0201 1980.32,1586.61 r180 bottom
C157 "GRM033R71E102KA01D" 0201 2043.31,1681.1 r0 bottom
C158 "GRM033R71E102KA01D" 0201 2279.53,1507.87 r90 bottom
C159 "GRM033R71E102KA01D" 0201 2216.54,1507.87 r90 bottom
C160 "GRM033R71E102KA01D" 0201 2248.03,1507.87 r270 bottom
C161 "GRM033R71E102KA01D" 0201 2279.53,1570.87 r90 bottom
C162 "GRM033R71E102KA01D" 0201 2830.71,1996.06 r180 bottom
C163 "GRM033R71E102KA01D" 0201 2830.71,1870.08 r0 bottom
C164 "GRM033R71E102KA01D" 0201 2830.71,1744.09 r0 bottom
C165 "GRM033R71E102KA01D" 0201 2830.71,1618.11 r0 bottom
C166 "GRM033R71E102KA01D" 0201 2830.71,1523.62 r0 bottom
C167 "GRM033R71E102KA01D" 0201 2688.98,1976.38 r90 bottom
C168 "GRM033R71E102KA01D" 0201 2688.98,1917.32 r90 bottom
C169 "GRM033R71E102KA01D" 0201 2720.47,1948.82 r90 bottom
C170 "GRM033R71E102KA01D" 0201 2657.48,1822.83 r90 bottom
C171 "GRM033R71E102KA01D" 0201 2688.98,1854.33 r90 bottom
C172 "GRM033R71E102KA01D" 0201 2720.47,1854.33 r270 bottom
C173 "GRM033R71E102KA01D" 0201 2720.47,1791.34 r270 bottom
C174 "GRM033R71E102KA01D" 0201 2688.98,1791.34 r90 bottom
C175 "GRM033R71E102KA01D" 0201 2657.48,1759.84 r90 bottom
C176 "GRM033R71E102KA01D" 0201 2657.48,1696.85 r90 bottom
C177 "GRM033R71E102KA01D" 0201 2688.98,1696.85 r270 bottom
C178 "GRM033R71E102KA01D" 0201 2657.48,1633.86 r90 bottom
C179 "GRM033R71E102KA01D" 0201 2720.47,1696.85 r90 bottom
C180 "GRM033R71E102KA01D" 0201 2688.98,1633.86 r270 bottom
C181 "GRM033R71E102KA01D" 0201 2720.47,1633.86 r90 bottom
C182 "GRM033R71E102KA01D" 0201 1996.06,1350.39 r90 bottom
C183 "GRM033R71E102KA01D" 0201 5018,326 r90 top
C184 "GRM033R71E102KA01D" 0201 2074.8,1429.13 r180 bottom
C185 "GRM033R71E102KA01D" 0201 2043.31,1523.62 r180 bottom
C186 "GRM033R71E102KA01D" 0201 2185.04,1381.89 r270 bottom
C187 "GRM033R71E102KA01D" 0201 1964.57,1350.39 r270 bottom
C188 "GRM033R71E102KA01D" 0201 2437.01,2169.29 r270 bottom
C189 "GRM033R71E102KA01D" 0201 2500,2169.29 r90 bottom
C190 "GRM033R71E102KA01D" 0201 2562.99,2169.29 r270 bottom
C191 "GRM033R71E102KA01D" 0201 2625.98,2169.29 r90 bottom
C192 "GRM033R71E102KA01D" 0201 2688.98,2169.29 r270 bottom
C193 "GRM033R71E102KA01D" 0201 2751.97,2169.29 r90 bottom
C194 "GRM033R71E102KA01D" 0201 2814.96,2169.29 r270 bottom
C195 "GRM033R71E102KA01D" 0201 2846.46,2232.28 r270 bottom
C196 "GRM033R71E102KA01D" 0201 2877.95,2232.28 r90 bottom
C197 "GRM033R71E102KA01D" 0201 2342.52,2169.29 r90 bottom
C198 "GRM033R71E102KA01D" 0201 2248.03,2043.31 r90 bottom
C199 "GRM033R71E102KA01D" 0201 2216.54,2043.31 r270 bottom
C200 "GRM033R71E102KA01D" 0201 2531.5,1980.32 r270 bottom
C201 "GRM033R71E102KA01D" 0201 1980.32,2248.03 r180 bottom
C202 "GRM033R71E102KA01D" 0201 1948.82,2216.54 r180 bottom
C203 "GRM033R71E102KA01D" 0201 2216.54,2169.29 r90 bottom
C204 "GRM033R71E102KA01D" 0201 2153.54,2169.29 r270 bottom
C205 "GRM033R71E102KA01D" 0201 2090.55,2169.29 r90 bottom
C206 "GRM033R71E102KA01D" 0201 2027.56,2169.29 r270 bottom
C207 "GRM033R71E102KA01D" 0201 2279.53,2169.29 r270 bottom
C208 "GRM033R71E102KA01D" 0201 2342.52,2043.31 r270 bottom
C209 "GRM033R71E102KA01D" 0201 2311.02,2043.31 r90 bottom
C210 "GRM033R71E102KA01D" 0201 2405.51,2043.31 r270 bottom
C211 "GRM033R71E102KA01D" 0201 2374.02,2043.31 r90 bottom
C212 "GRM033R71E102KA01D" 0201 2437.01,2043.31 r90 bottom
C213 "GRM033R71E102KA01D" 0201 2500,2043.31 r90 bottom
C214 "GRM033R71E102KA01D" 0201 2531.5,2043.31 r270 bottom
C215 "GRM033R71E102KA01D" 0201 2562.99,2043.31 r90 bottom
C216 "GRM033R71E102KA01D" 0201 2625.98,2043.31 r90 bottom
C217 "GRM033R71E102KA01D" 0201 2688.98,2043.31 r90 bottom
C218 "GRM033R71E102KA01D" 0201 2720.47,2074.8 r90 bottom
C219 "GRM033R71E102KA01D" 0201 2137.8,1618.11 r180 bottom
C220 "GRM033R71E102KA01D" 0201 2279.53,2076.28 r90 bottom
C221 "GRM033R71E102KA01D" 0201 2232.28,1996.06 r0 bottom
C222 "GRM033R71E102KA01D" 0201 2421.26,1996.06 r0 bottom
C223 "GRM033R71E102KA01D" 0201 2326.77,1996.06 r180 bottom
C224 "GRM033R71E102KA01D" 0201 2153.54,1980.32 r270 bottom
C225 "GRM033R71E102KA01D" 0201 2122.05,2043.31 r90 bottom
C226 "GRM033R71E102KA01D" 0201 2153.54,2043.31 r270 bottom
C227 "GRM033R71E102KA01D" 0201 2185.04,2043.31 r90 bottom
C228 "6TPE100MI" 0402 2930,2410 r90 top
C231 "GRM152B30J104KE19" 0402 2830,2410 r90 top
C232 "GRM152B30J104KE19" 0402 2880,2410 r270 top
C233 "GRM152B30J104KE19" 0402 2100,2410 r90 top
C234 "GRM152B30J104KE19" 0402 2150,2410 r270 top
C235 "GRM033R71E102KA01D" 0201 2342.52,1570.87 r90 bottom
C236 "GRM033R71E102KA01D" 0201 2374.02,1570.87 r270 bottom
C237 "GRM033R71E102KA01D" 0201 2405.51,1570.87 r90 bottom
C238 "GRM033R71E102KA01D" 0201 2437.01,1570.87 r270 bottom
C239 "GRM033R71E102KA01D" 0201 2468.5,1570.87 r90 bottom
C240 "GRM033R71E102KA01D" 0201 2500,1570.87 r270 bottom
C241 "GRM033R71E102KA01D" 0201 2531.5,1570.87 r90 bottom
C242 "GRM152B30J104KE19" 0402 2620,1260 r0 top
C243 "GRM152B30J104KE19" 0402 2500,1260 r180 top
C244 "GRM033R71E102KA01D" 0201 2622.99,1100 r0 top
C245 "GRM152B30J104KE19" 0402 2623.62,1060 r0 top
C246 "GRM033R71E102KA01D" 0201 2500,1100 r180 top
C247 "GRM152B30J104KE19" 0402 2500,1061.5 r180 top
C248 "GRM033R71E102KA01D" 0201 8558,866 r90 top
C249 "GRM033R71E102KA01D" 0201 8768,866 r90 top
C250 "GRM152B30J104KE19" 0402 8988,786 r90 top
C251 "GRM152B30J104KE19" 0402 9198,786 r90 top
C252 "GRM033R71E102KA01D" 0201 7588,866 r90 top
C253 "GRM033R71E102KA01D" 0201 7798,866 r90 top
C254 "GRM152B30J104KE19" 0402 8018,786 r90 top
C255 "GRM152B30J104KE19" 0402 8228,786 r90 top
C256 "GRM033R71E102KA01D" 0201 6618,866 r90 top
C257 "GRM033R71E102KA01D" 0201 6828,866 r90 top
C258 "GRM152B30J104KE19" 0402 7048,786 r90 top
C259 "GRM152B30J104KE19" 0402 7258,786 r90 top
C260 "GRM152B30J104KE19" 0402 5868,786 r90 top
C261 "GRM152B30J104KE19" 0402 6088,786 r90 top
C262 "GRM152B30J104KE19" 0402 6278,786 r90 top
C263 "GRM033R71E102KA01D" 0201 5130,870 r90 top
C264 "GRM033R71E102KA01D" 0201 5238,866 r90 top
C265 "GRM152B30J104KE19" 0402 5330,460 r90 top
C266 "GRM152B30J104KE19" 0402 5658,786 r90 top
C267 "GRM152B30J104KE19" 0402 6748,2416 r90 top
C268 "GRM033R71E102KA01D" 0201 2185.04,1980.32 r90 bottom
C269 "GRM033R71E102KA01D" 0201 2279.53,2011.81 r90 bottom
C270 "GRM033R71E102KA01D" 0201 2468.5,2011.81 r90 bottom
C271 "GRM033R71E102KA01D" 0201 5018,546 r90 top
C272 "GRM033R71E102KA01D" 0201 2594.49,2011.81 r90 bottom
C273 "GRM033R71E102KA01D" 0201 2357.01,2510 r180 top
C274 "GRM152B30J104KE19" 0402 2470,2350 r0 top
C275 "GRM152B30J104KE19" 0402 2463.62,2540 r0 top
C276 "GRM033R71E102KA01D" 0201 2460,2510 r0 top
C277 "GRM152B30J104KE19" 0402 2356.38,2350 r180 top
C278 "GRM152B30J104KE19" 0402 2353.62,2540 r180 top
C279 "GRM033R71E102KA01D" 0201 2657.48,2011.81 r90 bottom
C280 "GRM033R71E102KA01D" 0201 2712.99,2470 r0 top
C281 "GRM152B30J104KE19" 0402 2718.27,2354.49 r0 top
C282 "GRM152B30J104KE19" 0402 2638.27,2474.49 r180 top
C283 "GRM033R71E102KA01D" 0201 2641.73,1523.62 r0 bottom
C284 "GRM033R71E102KA01D" 0201 2547.24,1523.62 r180 bottom
C285 "GRM033R71E102KA01D" 0201 2484.25,1523.62 r180 bottom
C286 "GRM033R71E102KA01D" 0201 2421.26,1523.62 r180 bottom
C287 "GRM033R71E102KA01D" 0201 2358.27,1523.62 r180 bottom
C288 "GRM033R71E102KA01D" 0201 2311.02,1539.37 r90 bottom
C289 "GRM033R71E102KA01D" 0201 2380,1100 r0 top
C290 "GRM152B30J104KE19" 0402 2260,1260 r180 top
C291 "GRM152B30J104KE19" 0402 2260,1058.5 r180 top
C292 "GRM033R71E102KA01D" 0201 2260,1100 r180 top
C293 "GRM152B30J104KE19" 0402 2380,1260 r0 top
C294 "GRM152B30J104KE19" 0402 2380,1060 r0 top
C295 "GRM033R71E102KA01D" 0201 2704.72,1744.09 r180 bottom
C296 "GRM033R71E102KA01D" 0201 3100,1700 r270 top
C297 "GRM152B30J104KE19" 0402 2950,1696.38 r270 top
C298 "GRM152B30J104KE19" 0402 3140,1696.38 r270 top
C299 "GRM033R71E102KA01D" 0201 2311.02,1476.38 r90 bottom
C300 "GRM033R71E102KA01D" 0201 2142.99,1110 r180 top
C301 "GRM152B30J104KE19" 0402 2130,1250 r180 top
C302 "GRM152B30J104KE19" 0402 2140,1070 r180 top
C303 "GRM033R71E102KA01D" 0201 2767.72,1492.13 r0 bottom
C304 "GRM033R71E102KA01D" 0201 3100,1547.01 r90 top
C305 "GRM152B30J104KE19" 0402 2950,1550 r90 top
C306 "GRM152B30J104KE19" 0402 3140,1547.01 r90 top
C307 "GRM033R71E102KA01D" 0201 2751.97,1444.88 r270 bottom
C308 "GRM033R71E102KA01D" 0201 3100,1372 r270 top
C309 "GRM152B30J104KE19" 0402 2950,1372 r270 top
C310 "GRM152B30J104KE19" 0402 3140,1372 r270 top
FID1 "Fiducial" Fiducial10-20 640,3150 r0 top
FID2 "Fiducial" Fiducial10-20 640,300 r0 top
FID3 "Fiducial" Fiducial10-20 4320,300 r0 top
H1 "NY PMS 440 0025 PH" "NY PMS 440 0025 PH" 200,3250 r0 top locked
H2 "NY PMS 440 0025 PH" "NY PMS 440 0025 PH" 4750,3250 r0 top locked
H3 "NY PMS 440 0025 PH" "NY PMS 440 0025 PH" 200,200 r0 top locked
H4 "NY PMS 440 0025 PH" "NY PMS 440 0025 PH" 4750,200 r0 top locked
H5 "1902C" Keystone_1902C 200,3250 r180 bottom locked
H6 "1902C" Keystone_1902C 4750,3250 r180 bottom locked
H7 "1902C" Keystone_1902C 200,200 r180 bottom locked
H8 "1902C" Keystone_1902C 4750,200 r180 bottom locked
H9 "SJ-5303 (CLEAR)" Bumpon_SJ5003Transparent 790,2980 r180 bottom
H10 "SJ-5303 (CLEAR)" Bumpon_SJ5003Transparent 4190,2970 r180 bottom
H11 "SJ-5303 (CLEAR)" Bumpon_SJ5003Transparent 790,540 r180 bottom
H12 "SJ-5303 (CLEAR)" Bumpon_SJ5003Transparent 4180,540 r180 bottom
J1 "QSH-030-01-L-D-A" Samtec_QSH-030-01-X-D-A 8268,2116 r0 top
L1 "BLM18SG121TN1D" 0603 2560,1168.5 r270 top
L2 "BLM15AG121SN1D" 0402 9398,786 r90 top
L3 "BLM15AG121SN1D" 0402 8438,786 r90 top
L4 "BLM15AG121SN1D" 0402 7468,786 r90 top
L5 "BLM15AG121SN1D" 0402 5400,460 r90 top
L6 "BLM18SG121TN1D" 0603 2410,2420 r90 top
L7 "BLM15AG121SN1D" 0402 2676.06,2416.38 r90 top
L8 "BLM18SG121TN1D" 0603 2320,1168.5 r270 top
L9 "BLM15AG121SN1D" 0402 3030,1736.38 r0 top
L10 "BLM15AG121SN1D" 0402 2170,1170 r270 top
L11 "BLM15AG121SN1D" 0402 3030,1510 r0 top
L12 "BLM15AG121SN1D" 0402 3030,1412 r0 top
LBL1 "Size: 0.65\" x 0.20 \"" Label_650x200 1408,167 r0 top
Logo1 "Texas Instruments" TI_Stacked_SolderMask_Small 3240,140 r0 top
Logo2 "Pb-Free Symbol" Pb-Free_Overlay_Small 2050,290 r0 top
Logo3 "FCC disclaimer" FCC_disclaimer 2350,3380 r0 top
R1 "CRCW04024K75FKED" 0402 6458,1106 r90 top
R2 "CRCW04024K75FKED" 0402 6578,1106 r90 top
R3 "CRCW04024K75FKED" 0402 6708,1106 r90 top
R4 "CRCW04021K00FKED" 0402 6198,1106 r90 top
R5 "CRCW04021K00FKED" 0402 6328,1106 r90 top
R6 "CRCW04021K00FKED" 0402 5798,1106 r90 top
R7 "CRCW04021K00FKED" 0402 5938,1106 r90 top
R8 "CRCW04021K00FKED" 0402 6068,1106 r90 top
R9 "CRCW0402100RFKED" 0402 5508,1106 r90 top
R10 "CRCW040210R0FKED" 0402 5638,1106 r90 top
R11 "CRCW0402100RFKED" 0402 5358,1106 r90 top
R12 "CRCW04021K00FKED" 0402 5198,1106 r90 top
R13 "CRCW0402100RFKED" 0402 5120,1110 r90 top
R14 "CRCW040210R0FKED" 0402 5358,1426 r90 top
R15 "CRCW040210R0FKED" 0402 5198,1426 r90 top
R16 "CRCW040210R0FKED" 0402 5028,1426 r90 top
R17 "CRCW04024K75FKED" 0402 9018,2416 r90 top
R18 "CRCW0402100RFKED" 0402 8688,2416 r90 top
R19 "CRCW0402100RFKED" 0402 8858,2416 r90 top
R20 "CRCW040210R0FKED" 0402 7968,2416 r90 top
R21 "CRCW040210R0FKED" 0402 7808,2416 r90 top
R22 "CRCW040210R0FKED" 0402 7638,2416 r90 top
R23 "CRCW040210R0FKED" 0402 7468,2416 r90 top
R24 "CRCW040210R0FKED" 0402 7298,2416 r90 top
R25 "CRCW04024K75FKED" 0402 7128,2416 r90 top
R26 "CRCW040210R0FKED" 0402 6958,2416 r90 top
R27 "CRCW040210R0FKED" 0402 6208,2416 r90 top
R28 "CRCW040210R0FKED" 0402 6038,2416 r90 top
R29 "CRCW040210R0FKED" 0402 5868,2416 r90 top
R30 "CRCW040210R0FKED" 0402 5698,2416 r90 top
R31 "CRCW040210R0FKED" 0402 5538,2416 r90 top
R32 "CRCW040210R0FKED" 0402 5368,2416 r90 top
R33 "CRCW04024K75FKED" 0402 5028,2416 r90 top
R34 "CRCW040210R0FKED" 0402 5198,2416 r90 top
R35 "CRCW04023K00JNED" 0402 5198,2736 r90 top
R36 "CRCW04023K00JNED" 0402 5028,2736 r90 top
R37 "CRCW04023K00JNED" 0402 5198,3796 r90 top
R38 "CRCW04023K00JNED" 0402 5028,3796 r90 top
U1 "TCI6630K2L" BGA900C80P30X30_2500X2500X355 2405.51,1807.09 r0 top locked
U2 "SN74LVC244APW" PW0020A_N 6518,2396 r0 top
U3 "MT41K256M16HA-125" MICT-HA-96 5218,3306 r0 top
U4 "MT41K256M16HA-125" MICT-HA-96 5678,3306 r0 top
U5 "MT41K256M16HA-125" MICT-HA-96 6138,3306 r0 top
U6 "MT41K256M16HA-125" MICT-HA-96 6598,3306 r0 top
U7 "MT41K256M16HA-125" MICT-HA-96 7058,3306 r0 top
ZZ1 "This Assembly Note is for PCB labels only" AssemblyNoteLabel 185,3938 r0 top
ZZ2 "This Assembly Note will show in the PcbDoc and associated outputs" AssemblyNote 185,3829.11 r0 top
ZZ3 "This Assembly Note will show in the PcbDoc and associated outputs" AssemblyNote 185,3740.56 r0 top
ZZ4 "This Assembly Note will show in the PcbDoc and associated outputs" AssemblyNote 185,3652 r0 top

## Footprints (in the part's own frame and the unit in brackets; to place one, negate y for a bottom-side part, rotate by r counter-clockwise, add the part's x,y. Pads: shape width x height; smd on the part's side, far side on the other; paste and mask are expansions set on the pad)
0201 [mm] "Data from Kemet datasheet CC101_COM dated 7/28/11"
  rect 0.46x0.42 smd mask+0.048: 1(-0.33,0) 2(0.33,0)
  body extent -0.31,-0.16 0.31,0.16, height 0.26
0402 [mm] "0402 from SM-752 data"
  rect 0.8x0.6 smd: 1(-0.6,0) 2(0.6,0)
  silkscreen extent -1.22,-0.52 1.22,0.52, body extent -0.55,-0.3 0.55,0.3, height 0.6
0603 [mm] "0603 from SM-752 data"
  rect 1x0.95 smd: 1(-0.8,0) 2(0.8,0)
  silkscreen extent -1.52,-0.69 1.52,0.69, body extent -0.87,-0.47 0.87,0.47, height 0.85
AssemblyNote [mil] "Assembly Note"
AssemblyNoteLabel [mil] "Assembly Note for PCB Labels"
BGA900C80P30X30_2500X2500X355 [mm] "BGA, 900-Leads, Body 25.0x25.0mm,  Pitch 0.80mm"
  round 0.45 smd: A1(-11.6,11.6) A2(-10.8,11.6) A3(-10,11.6) A4(-9.2,11.6) A5(-8.4,11.6) A6(-7.6,11.6) A7(-6.8,11.6) A8(-6,11.6) A9(-5.2,11.6) A10(-4.4,11.6) A11(-3.6,11.6) A12(-2.8,11.6) A13(-2,11.6) A14(-1.2,11.6) A15(-0.4,11.6) A16(0.4,11.6) A17(1.2,11.6) A18(2,11.6) A19(2.8,11.6) A20(3.6,11.6) A21(4.4,11.6) A22(5.2,11.6) A23(6,11.6) A24(6.8,11.6) A25(7.6,11.6) A26(8.4,11.6) A27(9.2,11.6) A28(10,11.6) A29(10.8,11.6) A30(11.6,11.6) AA1(-11.6,-4.4) AA2(-10.8,-4.4) AA3(-10,-4.4) AA4(-9.2,-4.4) AA5(-8.4,-4.4) AA6(-7.6,-4.4) AA7(-6.8,-4.4) AA8(-6,-4.4) AA9(-5.2,-4.4) AA10(-4.4,-4.4) AA11(-3.6,-4.4) AA12(-2.8,-4.4) AA13(-2,-4.4) AA14(-1.2,-4.4) AA15(-0.4,-4.4) AA16(0.4,-4.4) AA17(1.2,-4.4) AA18(2,-4.4) AA19(2.8,-4.4) AA20(3.6,-4.4) AA21(4.4,-4.4) AA22(5.2,-4.4) AA23(6,-4.4) AA24(6.8,-4.4) AA25(7.6,-4.4) AA26(8.4,-4.4) AA27(9.2,-4.4) AA28(10,-4.4) AA29(10.8,-4.4) AA30(11.6,-4.4) AB1(-11.6,-5.2) AB2(-10.8,-5.2) AB3(-10,-5.2) AB4(-9.2,-5.2) AB5(-8.4,-5.2) AB6(-7.6,-5.2) AB7(-6.8,-5.2) AB8(-6,-5.2) AB9(-5.2,-5.2) AB10(-4.4,-5.2) AB11(-3.6,-5.2) AB12(-2.8,-5.2) AB13(-2,-5.2) AB14(-1.2,-5.2) AB15(-0.4,-5.2) AB16(0.4,-5.2) AB17(1.2,-5.2) AB18(2,-5.2) AB19(2.8,-5.2) AB20(3.6,-5.2) AB21(4.4,-5.2) AB22(5.2,-5.2) AB23(6,-5.2) AB24(6.8,-5.2) AB25(7.6,-5.2) AB26(8.4,-5.2) AB27(9.2,-5.2) AB28(10,-5.2) AB29(10.8,-5.2) AB30(11.6,-5.2) AC1(-11.6,-6) AC2(-10.8,-6) AC3(-10,-6) AC4(-9.2,-6) AC5(-8.4,-6) AC6(-7.6,-6) AC7(-6.8,-6) AC8(-6,-6) AC9(-5.2,-6) AC10(-4.4,-6) AC11(-3.6,-6) AC12(-2.8,-6) AC13(-2,-6) AC14(-1.2,-6) AC15(-0.4,-6) AC16(0.4,-6) AC17(1.2,-6) AC18(2,-6) AC19(2.8,-6) AC20(3.6,-6) AC21(4.4,-6) AC22(5.2,-6) AC23(6,-6) AC24(6.8,-6) AC25(7.6,-6) AC26(8.4,-6) AC27(9.2,-6) AC28(10,-6) AC29(10.8,-6) AC30(11.6,-6) AD1(-11.6,-6.8) AD2(-10.8,-6.8) AD3(-10,-6.8) AD4(-9.2,-6.8) AD5(-8.4,-6.8) AD6(-7.6,-6.8) AD7(-6.8,-6.8) AD8(-6,-6.8) AD9(-5.2,-6.8) AD10(-4.4,-6.8) AD11(-3.6,-6.8) AD12(-2.8,-6.8) AD13(-2,-6.8) AD14(-1.2,-6.8) AD15(-0.4,-6.8) AD16(0.4,-6.8) AD17(1.2,-6.8) AD18(2,-6.8) AD19(2.8,-6.8) AD20(3.6,-6.8) AD21(4.4,-6.8) AD22(5.2,-6.8) AD23(6,-6.8) AD24(6.8,-6.8) AD25(7.6,-6.8) AD26(8.4,-6.8) AD27(9.2,-6.8) AD28(10,-6.8) AD29(10.8,-6.8) AD30(11.6,-6.8) AE1(-11.6,-7.6) AE2(-10.8,-7.6) AE3(-10,-7.6) AE4(-9.2,-7.6) AE5(-8.4,-7.6) AE6(-7.6,-7.6) AE7(-6.8,-7.6) AE8(-6,-7.6) AE9(-5.2,-7.6) AE10(-4.4,-7.6) AE11(-3.6,-7.6) AE12(-2.8,-7.6) AE13(-2,-7.6) AE14(-1.2,-7.6) AE15(-0.4,-7.6) AE16(0.4,-7.6) AE17(1.2,-7.6) AE18(2,-7.6) AE19(2.8,-7.6) AE20(3.6,-7.6) AE21(4.4,-7.6) AE22(5.2,-7.6) AE23(6,-7.6) AE24(6.8,-7.6) AE25(7.6,-7.6) AE26(8.4,-7.6) AE27(9.2,-7.6) AE28(10,-7.6) AE29(10.8,-7.6) AE30(11.6,-7.6) AF1(-11.6,-8.4) AF2(-10.8,-8.4) AF3(-10,-8.4) AF4(-9.2,-8.4) AF5(-8.4,-8.4) AF6(-7.6,-8.4) AF7(-6.8,-8.4) AF8(-6,-8.4) AF9(-5.2,-8.4) AF10(-4.4,-8.4) AF11(-3.6,-8.4) AF12(-2.8,-8.4) AF13(-2,-8.4) AF14(-1.2,-8.4) AF15(-0.4,-8.4) AF16(0.4,-8.4) AF17(1.2,-8.4) AF18(2,-8.4) AF19(2.8,-8.4) AF20(3.6,-8.4) AF21(4.4,-8.4) AF22(5.2,-8.4) AF23(6,-8.4) AF24(6.8,-8.4) AF25(7.6,-8.4) AF26(8.4,-8.4) AF27(9.2,-8.4) AF28(10,-8.4) AF29(10.8,-8.4) AF30(11.6,-8.4) AG1(-11.6,-9.2) AG2(-10.8,-9.2) AG3(-10,-9.2) AG4(-9.2,-9.2) AG5(-8.4,-9.2) AG6(-7.6,-9.2) AG7(-6.8,-9.2) AG8(-6,-9.2) AG9(-5.2,-9.2) AG10(-4.4,-9.2) AG11(-3.6,-9.2) AG12(-2.8,-9.2) AG13(-2,-9.2) AG14(-1.2,-9.2) AG15(-0.4,-9.2) AG16(0.4,-9.2) AG17(1.2,-9.2) AG18(2,-9.2) AG19(2.8,-9.2) AG20(3.6,-9.2) AG21(4.4,-9.2) AG22(5.2,-9.2) AG23(6,-9.2) AG24(6.8,-9.2) AG25(7.6,-9.2) AG26(8.4,-9.2) AG27(9.2,-9.2) AG28(10,-9.2) AG29(10.8,-9.2) AG30(11.6,-9.2) AH1(-11.6,-10) AH2(-10.8,-10) AH3(-10,-10) AH4(-9.2,-10) AH5(-8.4,-10) AH6(-7.6,-10) AH7(-6.8,-10) AH8(-6,-10) AH9(-5.2,-10) AH10(-4.4,-10) AH11(-3.6,-10) AH12(-2.8,-10) AH13(-2,-10) AH14(-1.2,-10) AH15(-0.4,-10) AH16(0.4,-10) AH17(1.2,-10) AH18(2,-10) AH19(2.8,-10) AH20(3.6,-10) AH21(4.4,-10) AH22(5.2,-10) AH23(6,-10) AH24(6.8,-10) AH25(7.6,-10) AH26(8.4,-10) AH27(9.2,-10) AH28(10,-10) AH29(10.8,-10) AH30(11.6,-10) AJ1(-11.6,-10.8) AJ2(-10.8,-10.8) AJ3(-10,-10.8) AJ4(-9.2,-10.8) AJ5(-8.4,-10.8) AJ6(-7.6,-10.8) AJ7(-6.8,-10.8) AJ8(-6,-10.8) AJ9(-5.2,-10.8) AJ10(-4.4,-10.8) AJ11(-3.6,-10.8) AJ12(-2.8,-10.8) AJ13(-2,-10.8) AJ14(-1.2,-10.8) AJ15(-0.4,-10.8) AJ16(0.4,-10.8) AJ17(1.2,-10.8) AJ18(2,-10.8) AJ19(2.8,-10.8) AJ20(3.6,-10.8) AJ21(4.4,-10.8) AJ22(5.2,-10.8) AJ23(6,-10.8) AJ24(6.8,-10.8) AJ25(7.6,-10.8) AJ26(8.4,-10.8) AJ27(9.2,-10.8) AJ28(10,-10.8) AJ29(10.8,-10.8) AJ30(11.6,-10.8) AK1(-11.6,-11.6) AK2(-10.8,-11.6) AK3(-10,-11.6) AK4(-9.2,-11.6) AK5(-8.4,-11.6) AK6(-7.6,-11.6) AK7(-6.8,-11.6) AK8(-6,-11.6) AK9(-5.2,-11.6) AK10(-4.4,-11.6) AK11(-3.6,-11.6) AK12(-2.8,-11.6) AK13(-2,-11.6) AK14(-1.2,-11.6) AK15(-0.4,-11.6) AK16(0.4,-11.6) AK17(1.2,-11.6) AK18(2,-11.6) AK19(2.8,-11.6) AK20(3.6,-11.6) AK21(4.4,-11.6) AK22(5.2,-11.6) AK23(6,-11.6) AK24(6.8,-11.6) AK25(7.6,-11.6) AK26(8.4,-11.6) AK27(9.2,-11.6) AK28(10,-11.6) AK29(10.8,-11.6) AK30(11.6,-11.6) B1(-11.6,10.8) B2(-10.8,10.8) B3(-10,10.8) B4(-9.2,10.8) B5(-8.4,10.8) B6(-7.6,10.8) B7(-6.8,10.8) B8(-6,10.8) B9(-5.2,10.8) B10(-4.4,10.8) B11(-3.6,10.8) B12(-2.8,10.8) B13(-2,10.8) B14(-1.2,10.8) B15(-0.4,10.8) B16(0.4,10.8) B17(1.2,10.8) B18(2,10.8) B19(2.8,10.8) B20(3.6,10.8) B21(4.4,10.8) B22(5.2,10.8) B23(6,10.8) B24(6.8,10.8) B25(7.6,10.8) B26(8.4,10.8) B27(9.2,10.8) B28(10,10.8) B29(10.8,10.8) B30(11.6,10.8) C1(-11.6,10) C2(-10.8,10) C3(-10,10) C4(-9.2,10) C5(-8.4,10) C6(-7.6,10) C7(-6.8,10) C8(-6,10) C9(-5.2,10) C10(-4.4,10) C11(-3.6,10) C12(-2.8,10) C13(-2,10) C14(-1.2,10) C15(-0.4,10) C16(0.4,10) C17(1.2,10) C18(2,10) C19(2.8,10) C20(3.6,10) C21(4.4,10) C22(5.2,10) C23(6,10) C24(6.8,10) C25(7.6,10) C26(8.4,10) C27(9.2,10) C28(10,10) C29(10.8,10) C30(11.6,10) D1(-11.6,9.2) D2(-10.8,9.2) D3(-10,9.2) D4(-9.2,9.2) D5(-8.4,9.2) D6(-7.6,9.2) D7(-6.8,9.2) D8(-6,9.2) D9(-5.2,9.2) D10(-4.4,9.2) D11(-3.6,9.2) D12(-2.8,9.2) D13(-2,9.2) D14(-1.2,9.2) D15(-0.4,9.2) D16(0.4,9.2) D17(1.2,9.2) D18(2,9.2) D19(2.8,9.2) D20(3.6,9.2) D21(4.4,9.2) D22(5.2,9.2) D23(6,9.2) D24(6.8,9.2) D25(7.6,9.2) D26(8.4,9.2) D27(9.2,9.2) D28(10,9.2) D29(10.8,9.2) D30(11.6,9.2) E1(-11.6,8.4) E2(-10.8,8.4) E3(-10,8.4) E4(-9.2,8.4) E5(-8.4,8.4) E6(-7.6,8.4) E7(-6.8,8.4) E8(-6,8.4) E9(-5.2,8.4) E10(-4.4,8.4) E11(-3.6,8.4) E12(-2.8,8.4) E13(-2,8.4) E14(-1.2,8.4) E15(-0.4,8.4) E16(0.4,8.4) E17(1.2,8.4) E18(2,8.4) E19(2.8,8.4) E20(3.6,8.4) E21(4.4,8.4) E22(5.2,8.4) E23(6,8.4) E24(6.8,8.4) E25(7.6,8.4) E26(8.4,8.4) E27(9.2,8.4) E28(10,8.4) E29(10.8,8.4) E30(11.6,8.4) F1(-11.6,7.6) F2(-10.8,7.6) F3(-10,7.6) F4(-9.2,7.6) F5(-8.4,7.6) F6(-7.6,7.6) F7(-6.8,7.6) F8(-6,7.6) F9(-5.2,7.6) F10(-4.4,7.6) F11(-3.6,7.6) F12(-2.8,7.6) F13(-2,7.6) F14(-1.2,7.6) F15(-0.4,7.6) F16(0.4,7.6) F17(1.2,7.6) F18(2,7.6) F19(2.8,7.6) F20(3.6,7.6) F21(4.4,7.6) F22(5.2,7.6) F23(6,7.6) F24(6.8,7.6) F25(7.6,7.6) F26(8.4,7.6) F27(9.2,7.6) F28(10,7.6) F29(10.8,7.6) F30(11.6,7.6) G1(-11.6,6.8) G2(-10.8,6.8) G3(-10,6.8) G4(-9.2,6.8) G5(-8.4,6.8) G6(-7.6,6.8) G7(-6.8,6.8) G8(-6,6.8) G9(-5.2,6.8) G10(-4.4,6.8) G11(-3.6,6.8) G12(-2.8,6.8) G13(-2,6.8) G14(-1.2,6.8) G15(-0.4,6.8) G16(0.4,6.8) G17(1.2,6.8) G18(2,6.8) G19(2.8,6.8) G20(3.6,6.8) G21(4.4,6.8) G22(5.2,6.8) G23(6,6.8) G24(6.8,6.8) G25(7.6,6.8) G26(8.4,6.8) G27(9.2,6.8) G28(10,6.8) G29(10.8,6.8) G30(11.6,6.8) H1(-11.6,6) H2(-10.8,6) H3(-10,6) H4(-9.2,6) H5(-8.4,6) H6(-7.6,6) H7(-6.8,6) H8(-6,6) H9(-5.2,6) H10(-4.4,6) H11(-3.6,6) H12(-2.8,6) H13(-2,6) H14(-1.2,6) H15(-0.4,6) H16(0.4,6) H17(1.2,6) H18(2,6) H19(2.8,6) H20(3.6,6) H21(4.4,6) H22(5.2,6) H23(6,6) H24(6.8,6) H25(7.6,6) H26(8.4,6) H27(9.2,6) H28(10,6) H29(10.8,6) H30(11.6,6) J1(-11.6,5.2) J2(-10.8,5.2) J3(-10,5.2) J4(-9.2,5.2) J5(-8.4,5.2) J6(-7.6,5.2) J7(-6.8,5.2) J8(-6,5.2) J9(-5.2,5.2) J10(-4.4,5.2) J11(-3.6,5.2) J12(-2.8,5.2) J13(-2,5.2) J14(-1.2,5.2) J15(-0.4,5.2) J16(0.4,5.2) J17(1.2,5.2) J18(2,5.2) J19(2.8,5.2) J20(3.6,5.2) J21(4.4,5.2) J22(5.2,5.2) J23(6,5.2) J24(6.8,5.2) J25(7.6,5.2) J26(8.4,5.2) J27(9.2,5.2) J28(10,5.2) J29(10.8,5.2) J30(11.6,5.2) K1(-11.6,4.4) K2(-10.8,4.4) K3(-10,4.4) K4(-9.2,4.4) K5(-8.4,4.4) K6(-7.6,4.4) K7(-6.8,4.4) K8(-6,4.4) K9(-5.2,4.4) K10(-4.4,4.4) K11(-3.6,4.4) K12(-2.8,4.4) K13(-2,4.4) K14(-1.2,4.4) K15(-0.4,4.4) K16(0.4,4.4) K17(1.2,4.4) K18(2,4.4) K19(2.8,4.4) K20(3.6,4.4) K21(4.4,4.4) K22(5.2,4.4) K23(6,4.4) K24(6.8,4.4) K25(7.6,4.4) K26(8.4,4.4) K27(9.2,4.4) K28(10,4.4) K29(10.8,4.4) K30(11.6,4.4) L1(-11.6,3.6) L2(-10.8,3.6) L3(-10,3.6) L4(-9.2,3.6) L5(-8.4,3.6) L6(-7.6,3.6) L7(-6.8,3.6) L8(-6,3.6) L9(-5.2,3.6) L10(-4.4,3.6) L11(-3.6,3.6) L12(-2.8,3.6) L13(-2,3.6) L14(-1.2,3.6) L15(-0.4,3.6) L16(0.4,3.6) L17(1.2,3.6) L18(2,3.6) L19(2.8,3.6) L20(3.6,3.6) L21(4.4,3.6) L22(5.2,3.6) L23(6,3.6) L24(6.8,3.6) L25(7.6,3.6) L26(8.4,3.6) L27(9.2,3.6) L28(10,3.6) L29(10.8,3.6) L30(11.6,3.6) M1(-11.6,2.8) M2(-10.8,2.8) M3(-10,2.8) M4(-9.2,2.8) M5(-8.4,2.8) M6(-7.6,2.8) M7(-6.8,2.8) M8(-6,2.8) M9(-5.2,2.8) M10(-4.4,2.8) M11(-3.6,2.8) M12(-2.8,2.8) M13(-2,2.8) M14(-1.2,2.8) M15(-0.4,2.8) M16(0.4,2.8) M17(1.2,2.8) M18(2,2.8) M19(2.8,2.8) M20(3.6,2.8) M21(4.4,2.8) M22(5.2,2.8) M23(6,2.8) M24(6.8,2.8) M25(7.6,2.8) M26(8.4,2.8) M27(9.2,2.8) M28(10,2.8) M29(10.8,2.8) M30(11.6,2.8) N1(-11.6,2) N2(-10.8,2) N3(-10,2) N4(-9.2,2) N5(-8.4,2) N6(-7.6,2) N7(-6.8,2) N8(-6,2) N9(-5.2,2) N10(-4.4,2) N11(-3.6,2) N12(-2.8,2) N13(-2,2) N14(-1.2,2) N15(-0.4,2) N16(0.4,2) N17(1.2,2) N18(2,2) N19(2.8,2) N20(3.6,2) N21(4.4,2) N22(5.2,2) N23(6,2) N24(6.8,2) N25(7.6,2) N26(8.4,2) N27(9.2,2) N28(10,2) N29(10.8,2) N30(11.6,2) P1(-11.6,1.2) P2(-10.8,1.2) P3(-10,1.2) P4(-9.2,1.2) P5(-8.4,1.2) P6(-7.6,1.2) P7(-6.8,1.2) P8(-6,1.2) P9(-5.2,1.2) P10(-4.4,1.2) P11(-3.6,1.2) P12(-2.8,1.2) P13(-2,1.2) P14(-1.2,1.2) P15(-0.4,1.2) P16(0.4,1.2) P17(1.2,1.2) P18(2,1.2) P19(2.8,1.2) P20(3.6,1.2) P21(4.4,1.2) P22(5.2,1.2) P23(6,1.2) P24(6.8,1.2) P25(7.6,1.2) P26(8.4,1.2) P27(9.2,1.2) P28(10,1.2) P29(10.8,1.2) P30(11.6,1.2) R1(-11.6,0.4) R2(-10.8,0.4) R3(-10,0.4) R4(-9.2,0.4) R5(-8.4,0.4) R6(-7.6,0.4) R7(-6.8,0.4) R8(-6,0.4) R9(-5.2,0.4) R10(-4.4,0.4) R11(-3.6,0.4) R12(-2.8,0.4) R13(-2,0.4) R14(-1.2,0.4) R15(-0.4,0.4) R16(0.4,0.4) R17(1.2,0.4) R18(2,0.4) R19(2.8,0.4) R20(3.6,0.4) R21(4.4,0.4) R22(5.2,0.4) R23(6,0.4) R24(6.8,0.4) R25(7.6,0.4) R26(8.4,0.4) R27(9.2,0.4) R28(10,0.4) R29(10.8,0.4) R30(11.6,0.4) T1(-11.6,-0.4) T2(-10.8,-0.4) T3(-10,-0.4) T4(-9.2,-0.4) T5(-8.4,-0.4) T6(-7.6,-0.4) T7(-6.8,-0.4) T8(-6,-0.4) T9(-5.2,-0.4) T10(-4.4,-0.4) T11(-3.6,-0.4) T12(-2.8,-0.4) T13(-2,-0.4) T14(-1.2,-0.4) T15(-0.4,-0.4) T16(0.4,-0.4) T17(1.2,-0.4) T18(2,-0.4) T19(2.8,-0.4) T20(3.6,-0.4) T21(4.4,-0.4) T22(5.2,-0.4) T23(6,-0.4) T24(6.8,-0.4) T25(7.6,-0.4) T26(8.4,-0.4) T27(9.2,-0.4) T28(10,-0.4) T29(10.8,-0.4) T30(11.6,-0.4) U1(-11.6,-1.2) U2(-10.8,-1.2) U3(-10,-1.2) U4(-9.2,-1.2) U5(-8.4,-1.2) U6(-7.6,-1.2) U7(-6.8,-1.2) U8(-6,-1.2) U9(-5.2,-1.2) U10(-4.4,-1.2) U11(-3.6,-1.2) U12(-2.8,-1.2) U13(-2,-1.2) U14(-1.2,-1.2) U15(-0.4,-1.2) U16(0.4,-1.2) U17(1.2,-1.2) U18(2,-1.2) U19(2.8,-1.2) U20(3.6,-1.2) U21(4.4,-1.2) U22(5.2,-1.2) U23(6,-1.2) U24(6.8,-1.2) U25(7.6,-1.2) U26(8.4,-1.2) U27(9.2,-1.2) U28(10,-1.2) U29(10.8,-1.2) U30(11.6,-1.2) V1(-11.6,-2) V2(-10.8,-2) V3(-10,-2) V4(-9.2,-2) V5(-8.4,-2) V6(-7.6,-2) V7(-6.8,-2) V8(-6,-2) V9(-5.2,-2) V10(-4.4,-2) V11(-3.6,-2) V12(-2.8,-2) V13(-2,-2) V14(-1.2,-2) V15(-0.4,-2) V16(0.4,-2) V17(1.2,-2) V18(2,-2) V19(2.8,-2) V20(3.6,-2) V21(4.4,-2) V22(5.2,-2) V23(6,-2) V24(6.8,-2) V25(7.6,-2) V26(8.4,-2) V27(9.2,-2) V28(10,-2) V29(10.8,-2) V30(11.6,-2) W1(-11.6,-2.8) W2(-10.8,-2.8) W3(-10,-2.8) W4(-9.2,-2.8) W5(-8.4,-2.8) W6(-7.6,-2.8) W7(-6.8,-2.8) W8(-6,-2.8) W9(-5.2,-2.8) W10(-4.4,-2.8) W11(-3.6,-2.8) W12(-2.8,-2.8) W13(-2,-2.8) W14(-1.2,-2.8) W15(-0.4,-2.8) W16(0.4,-2.8) W17(1.2,-2.8) W18(2,-2.8) W19(2.8,-2.8) W20(3.6,-2.8) W21(4.4,-2.8) W22(5.2,-2.8) W23(6,-2.8) W24(6.8,-2.8) W25(7.6,-2.8) W26(8.4,-2.8) W27(9.2,-2.8) W28(10,-2.8) W29(10.8,-2.8) W30(11.6,-2.8) Y1(-11.6,-3.6) Y2(-10.8,-3.6) Y3(-10,-3.6) Y4(-9.2,-3.6) Y5(-8.4,-3.6) Y6(-7.6,-3.6) Y7(-6.8,-3.6) Y8(-6,-3.6) Y9(-5.2,-3.6) Y10(-4.4,-3.6) Y11(-3.6,-3.6) Y12(-2.8,-3.6) Y13(-2,-3.6) Y14(-1.2,-3.6) Y15(-0.4,-3.6) Y16(0.4,-3.6) Y17(1.2,-3.6) Y18(2,-3.6) Y19(2.8,-3.6) Y20(3.6,-3.6) Y21(4.4,-3.6) Y22(5.2,-3.6) Y23(6,-3.6) Y24(6.8,-3.6) Y25(7.6,-3.6) Y26(8.4,-3.6) Y27(9.2,-3.6) Y28(10,-3.6) Y29(10.8,-3.6) Y30(11.6,-3.6)
  silkscreen extent -13.27,-12.5 12.5,12.5, body extent -11.87,-11.88 11.88,11.87, height 3.55
Bumpon_SJ5003Transparent [mil] "3M Hemispherical Bumpon transparent"
  round 1 on Mech4: 0(0,0)
  silkscreen extent -228,-228 228,228, body extent -217,-218 219,218, height 197
FCC_disclaimer [mil]
Fiducial10-20 [mm]
  round 1 smd mask+0.5: 1(0,0)
  Top Layer keep-out circle w1.178: c0,0 r0.5
Keystone_1902C [mil] "Hex Standoff, 4-40 threaded, nylon"
  body extent -145,-126 146,126, height 501
Label_650x200 [mil] "Thermal Transfer Label"
  silkscreen extent -325,-100 325,100, body extent -326,-101 326,101, height 1
MICT-HA-96 [mm] "BGA, 96-Balls, Body 14x9mm, Pitch 0.8mm"
  round 0.4 smd: A1(-3.2,6) A2(-2.4,6) A3(-1.6,6) A7(1.6,6) A8(2.4,6) A9(3.2,6) B1(-3.2,5.2) B2(-2.4,5.2) B3(-1.6,5.2) B7(1.6,5.2) B8(2.4,5.2) B9(3.2,5.2) C1(-3.2,4.4) C2(-2.4,4.4) C3(-1.6,4.4) C7(1.6,4.4) C8(2.4,4.4) C9(3.2,4.4) D1(-3.2,3.6) D2(-2.4,3.6) D3(-1.6,3.6) D7(1.6,3.6) D8(2.4,3.6) D9(3.2,3.6) E1(-3.2,2.8) E2(-2.4,2.8) E3(-1.6,2.8) E7(1.6,2.8) E8(2.4,2.8) E9(3.2,2.8) F1(-3.2,2) F2(-2.4,2) F3(-1.6,2) F7(1.6,2) F8(2.4,2) F9(3.2,2) G1(-3.2,1.2) G2(-2.4,1.2) G3(-1.6,1.2) G7(1.6,1.2) G8(2.4,1.2) G9(3.2,1.2) H1(-3.2,0.4) H2(-2.4,0.4) H3(-1.6,0.4) H7(1.6,0.4) H8(2.4,0.4) H9(3.2,0.4) J1(-3.2,-0.4) J2(-2.4,-0.4) J3(-1.6,-0.4) J7(1.6,-0.4) J8(2.4,-0.4) J9(3.2,-0.4) K1(-3.2,-1.2) K2(-2.4,-1.2) K3(-1.6,-1.2) K7(1.6,-1.2) K8(2.4,-1.2) K9(3.2,-1.2) L1(-3.2,-2) L2(-2.4,-2) L3(-1.6,-2) L7(1.6,-2) L8(2.4,-2) L9(3.2,-2) M1(-3.2,-2.8) M2(-2.4,-2.8) M3(-1.6,-2.8) M7(1.6,-2.8) M8(2.4,-2.8) M9(3.2,-2.8) N1(-3.2,-3.6) N2(-2.4,-3.6) N3(-1.6,-3.6) N7(1.6,-3.6) N8(2.4,-3.6) N9(3.2,-3.6) P1(-3.2,-4.4) P2(-2.4,-4.4) P3(-1.6,-4.4) P7(1.6,-4.4) P8(2.4,-4.4) P9(3.2,-4.4) R1(-3.2,-5.2) R2(-2.4,-5.2) R3(-1.6,-5.2) R7(1.6,-5.2) R8(2.4,-5.2) R9(3.2,-5.2) T1(-3.2,-6) T2(-2.4,-6) T3(-1.6,-6) T7(1.6,-6) T8(2.4,-6) T9(3.2,-6)
  silkscreen extent -5.27,-7 4.5,7, body extent -4.5,-7 4.5,7, height 0.1
"NY PMS 440 0025 PH" [mm] "4-40 nylon screw and mounting hole"
  round 8 hole 3.2: 1(0,0)
  body extent -3.3,-3.3 3.3,3.3, height 2.69
Pb-Free_Overlay_Small [mil]
  silkscreen extent -46,-46 46,46
PW0020A_N [mm] "TSOP, 20-Leads, Body 6.5x4.4mm, Pitch 0.65mm, IPC Medium Density"
  oval 1.7x0.35 smd: 1(-2.85,2.925) 2(-2.85,2.275) 3(-2.85,1.625) 4(-2.85,0.975) 5(-2.85,0.325) 6(-2.85,-0.325) 7(-2.85,-0.975) 8(-2.85,-1.625) 9(-2.85,-2.275) 10(-2.85,-2.925) 11(2.85,-2.925) 12(2.85,-2.275) 13(2.85,-1.625) 14(2.85,-0.975) 15(2.85,-0.325) 16(2.85,0.325) 17(2.85,0.975) 18(2.85,1.625) 19(2.85,2.275) 20(2.85,2.925)
  silkscreen extent -3.57,-3.3 1.6,3.37, body extent -3.21,-3.25 3.21,3.25, height 0.99
Samtec_QSH-030-01-X-D-A [mm] "Receptacle, 0.5 mm, 30x2, TH"
  rect 2.27x0.279 smd: 1(-2.865,7.25) 2(2.865,7.25) 3(-2.865,6.75) 4(2.865,6.75) 5(-2.865,6.25) 6(2.865,6.25) 7(-2.865,5.75) 8(2.865,5.75) 9(-2.865,5.25) 10(2.865,5.25) 11(-2.865,4.75) 12(2.865,4.75) 13(-2.865,4.25) 14(2.865,4.25) 15(-2.865,3.75) 16(2.865,3.75) 17(-2.865,3.25) 18(2.865,3.25) 19(-2.865,2.75) 20(2.865,2.75) 21(-2.865,2.25) 22(2.865,2.25) 23(-2.865,1.75) 24(2.865,1.75) 25(-2.865,1.25) 26(2.865,1.25) 27(-2.865,0.75) 28(2.865,0.75) 29(-2.865,0.25) 30(2.865,0.25) 31(-2.865,-0.25) 32(2.865,-0.25) 33(-2.865,-0.75) 34(2.865,-0.75) 35(-2.865,-1.25) 36(2.865,-1.25) 37(-2.865,-1.75) 38(2.865,-1.75) 39(-2.865,-2.25) 40(2.865,-2.25) 41(-2.865,-2.75) 42(2.865,-2.75) 43(-2.865,-3.25) 44(2.865,-3.25) 45(-2.865,-3.75) 46(2.865,-3.75) 47(-2.865,-4.25) 48(2.865,-4.25) 49(-2.865,-4.75) 50(2.865,-4.75) 51(-2.865,-5.25) 52(2.865,-5.25) 53(-2.865,-5.75) 54(2.865,-5.75) 55(-2.865,-6.25) 56(2.865,-6.25) 57(-2.865,-6.75) 58(2.865,-6.75) 59(-2.865,-7.25) 60(2.865,-7.25)
  round 0 hole 1.02 unplated: MH1(2.67,10.065) MH2(2.67,-10.065)
  rect 0.43x2.54 smd: MP1(0,8.065) MP4(0,-8.065)
  rect 0.43x4.7 smd: MP2(0,3.175) MP3(0,-3.175)
  silkscreen extent -3.9,-10.66 3.62,10.66, body extent -3.75,-10.64 3.75,10.67, height 3.25
TI_Stacked_SolderMask_Small [mil]
  rect 900x250 smd paste-125 mask-125: 0(0,0)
